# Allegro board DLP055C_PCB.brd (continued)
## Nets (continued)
VX1_DATA6_N: C49.1 U15.D24(VX1_DATA6_N)
VX1_DATA6_P: C50.1 U15.C24(VX1_DATA6_P)
VX1_DATA7_N: C51.1 U15.B25(VX1_DATA7_N)
VX1_DATA7_P: C52.1 U15.A25(VX1_DATA7_P)
VX1_PROJ_ON: J3.22 J68.2
WRP_CAMERA_TRIG: J503.3 R675.1(N1)
N30083522: R673.2(N2) U15.AC28(SSP0_CSZ_2)
N30083525: R672.2(N2) U15.AC26(SSP0_CSZ_1)
N30120583: Q10.4(D4) R739.1 U555.28(ISEN)
N30120605: C752.1 U555.21(VCP)
N30120666: C756.2 U555.17(CP2)
N30120670: C756.1 U555.18(CP1)
N30120672: Q10.1(G) U555.26(GDC)
N30120689: D30.2(CATHODE) L515.1 Q10.3(S) U555.25(LXC)
N30120771: L515.2 R740.1 R742.2
N30120877: R742.1 R747.2 TP228.1 U555.30(/FBC)
N30121099: Q11.1(G) U555.33(GD2)
N30121105: Q11.3(S) R744.2 R750.2
N30121107: R750.1 R751.2 TP230.1 U555.32(FB2)
N30121177: R175.1 R184.2
N30121238: L516.1 R181.2 R184.1
N30121260: R175.2 U555.46(V2P5)
N30121264: D32.2(CATHODE) L516.2 R176.1
N30121280: C763.1 R179.2 R181.1
N30121294: R176.2 U555.41(LX25)
N30121351: L517.1 R752.1 R758.2
N30121367: L518.1 R754.2 R759.2
N30121371: R754.1 R756.2
N30121469: R752.2 R755.2
N30121485: D35.2(CATHODE) L517.2 U555.23(LX5)
N30121491: D36.2(CATHODE) L518.2 U555.43(LX33)
N30121519: R758.1 TP234.1 U555.24(V5)
N30121523: R759.1 TP235.1 U555.45(V3P3)
N30121878: C767.1 C768.1 C769.1 DN4.3 J515.1 U555.13(CTAP)
N30121880: R763.1 U555.5(TACH)
N30122104: R768.2 U555.12(OUTA)
N30122184: R769.2 U555.15(OUTB)
N30122241: C766.2 L519.1 R770.2
N30122253: R770.1 U555.11(VM)
N30122255: R771.2 U555.16(OUTC)
N30122286: R772.2 U555.1(DOUT)
N30122298: D37.2(CATHODE) L519.2 U555.10(VMSW)
N30122348: C771.2 J516.1 L520.2
N30122394: C772.2 R777.1 U555.8(GMIN)
N30122422: D40.2(CATHODE) L520.1 U555.40(F1SW)
N30122436: R776.2 U555.14(SENSE)
N30122458: C767.2 R773.2
N30122460: C768.2 R774.2
N30122462: C769.2 R775.2
N30122488: D39.2(CATHODE) L521.1 U555.39(F2SW)
N30122494: C770.2 J517.1 L521.2
N30122512: D38.2(CATHODE) L522.1 U555.38(F3SW)
N30122563: C18.2 J518.1 L522.2
N30125467: R778.1 U556.28(ISEN)
N30125481: C773.1 U556.21(VCP)
N30125519: C777.2 U556.17(CP2)
N30125523: C777.1 U556.18(CP1)
N30125543: R779.2 U556.25(LXC)
N30125602: R780.2 U556.41(LX25)
N30125636: R781.1 U556.23(LX5)
N30125638: R782.2 U556.43(LX33)
N30125770: C780.1 C781.1 C782.1 DN8.3 J519.1 U556.13(CTAP)
N30125772: R783.1 U556.5(TACH)
N30125789: R784.1 U556.6(OSC)
N30125944: R785.2 U556.12(OUTA)
N30126008: R786.2 U556.35(PWRGOOD)
N30126042: R787.2 U556.15(OUTB)
N30126057: R788.2 U556.34(POSENSE)
N30126109: R789.2 U556.1(DOUT)
N30126111: R790.2 U556.48(RESETZ)
N30126115: C779.2 L523.1 R791.2
N30126127: R791.1 U556.11(VM)
N30126129: R792.2 U556.16(OUTC)
N30126176: R793.2 U556.36(PMDINTZ)
N30126180: C785.2 J520.1 L524.2
N30126190: D41.2(CATHODE) L523.2 U556.10(VMSW)
N30126220: D44.2(CATHODE) L524.1 U556.40(F1SW)
N30126261: C786.2 R798.1 U556.8(GMIN)
N30126303: R797.2 U556.14(SENSE)
N30126331: D43.2(CATHODE) L525.1 U556.39(F2SW)
N30126337: C784.2 J521.1 L525.2
N30126343: C780.2 R794.2
N30126345: C781.2 R795.2
N30126347: C782.2 R796.2
N30126360: D42.2(CATHODE) L526.1 U556.38(F3SW)
N30126390: C783.2 J522.1 L526.2
N30128088: R799.1 U557.28(ISEN)
N30128102: C787.1 U557.21(VCP)
N30128140: C791.2 U557.17(CP2)
N30128144: C791.1 U557.18(CP1)
N30128164: R800.2 U557.25(LXC)
N30128223: R801.2 U557.41(LX25)
N30128257: R802.1 U557.23(LX5)
N30128259: R803.2 U557.43(LX33)
N30128391: C794.1 C795.1 C796.1 DN12.3 J523.1 U557.13(CTAP)
N30128393: R804.1 U557.5(TACH)
N30128410: R805.1 U557.6(OSC)
N30128565: R806.2 U557.12(OUTA)
N30128629: R807.2 U557.35(PWRGOOD)
N30128663: R808.2 U557.15(OUTB)
N30128678: R809.2 U557.34(POSENSE)
N30128730: R810.2 U557.1(DOUT)
N30128732: R811.2 U557.48(RESETZ)
N30128736: C793.2 L527.1 R812.2
N30128748: R812.1 U557.11(VM)
N30128750: R813.2 U557.16(OUTC)
N30128797: R814.2 U557.36(PMDINTZ)
N30128801: C799.2 J524.1 L528.2
N30128811: D45.2(CATHODE) L527.2 U557.10(VMSW)
N30128841: D48.2(CATHODE) L528.1 U557.40(F1SW)
N30128882: C800.2 R819.1 U557.8(GMIN)
N30128924: R818.2 U557.14(SENSE)
N30128952: D47.2(CATHODE) L529.1 U557.39(F2SW)
N30128958: C798.2 J525.1 L529.2
N30128964: C794.2 R815.2
N30128966: C795.2 R816.2
N30128968: C796.2 R817.2
N30128978: D46.2(CATHODE) L530.1 U557.38(F3SW)
N30129011: C797.2 J526.1 L530.2
N30131580: D49.3(CATHODE) FB1.2 FB2.2 J527.2 J528.2 Q12.S(SOURCE) R822.2 R823.2 R824.2 R826.1 TP244.1
N30131609: TP246.1 U519.1(G) U521.9(BFET) U522.4(G)
N30131654: R821.2 U519.2(S) U520.2(A) U568.2(A) U569.2(A)
N30131717: FB1.1 FB2.1 J529.1(V_IN)
N30131761: C801.1 U521.1(DV/DT)
N30131777: R820.1 R827.2 U521.2(EN/UVLO)
N30131888: R828.1 U521.10(ILIM)
N30131961: FB3.2 J529.2(GND#2)
N30131963: FB4.2 J529.3(GND#3)
N30131977: U521.6(OUT#6) U521.7(OUT#7) U521.8(OUT#8) U522.1(S#1) U522.2(S#2) U522.3(S#3)
N30132461: R831.2 U523.3(D)
N30132672: R833.1 U524.1(EN)
N30132680: C812.2 U524.7(VBST)
N30132682: C812.1 L531.1 U524.6(SW)
N30132740: C813.2 C814.2 C815.2 L531.2 R834.1 R836.2
N30132787: C816.2 U524.3(VREG5)
N30132791: C813.1 R108.2 R836.1 U524.2(VFB)
N30132852: C817.2 U524.4(SS)
N30132884: R835.2 U527.3(D)
N30132918: C818.2 U525.5(TADJ)
N30132924: C819.2 U526.5(TADJ)
N30133027: R837.2 U528.3(D)
N30133077: C820.1 U59.1(DV/DT)
N30133183: R838.1 U59.10(ILIM)
N30178636: R872.2 U538.3(IN+) VR1.2(WIPER)
N30178648: C832.2 J532.1 R873.1
N30178650: J532.2 R874.1 TP279.1 U538.2(IN-)
N30178830: R876.2 U566.5(IN+) VR2.2(WIPER)
N30178842: C834.2 J533.1 R877.1
N30178844: J533.2 R878.1 TP281.1 U566.6(IN-)
N30179022: R880.2 U539.3(IN+) VR3.2(WIPER)
N30179034: C836.2 J535.1 R881.1
N30179036: J535.2 R882.1 TP283.1 U539.2(IN-)

Pads without a net: D49 2; D51 2; FID 1; FID#2 1; FID#3 1; FID#4 1; FID#5 1; FID#6 1; J10 46 48; J17 9 10 11 12; J21 6; J70 6 10 12 13 14; J102 9; J103 2 6; J111 4 5; J501 17 19; SW5 2 4 6; U1 1 2; U4 27 28 30 55 56; U8 27 28 30 55 56; U11 1; U12 1; U13 1; U14 1; U15 AJ12 AJ19 B29 C28 C30 D30 R30 T26 T29; U16 1; U17 2 5; U18 1; U19 1; U20 1; U30 1 2; U33 1; U39 1; U40 1; U42 1; U48 1; U51 22 23; U58 1; U59 9; U501 1 2; U503 5 7; U520 1; U525 8; U529 1; U538 5 6 7; U539 5 6 7; U555 29; U556 26 29 33; U557 26 29 33; U558 1; U562 18; U563 1; U564 1; U566 1 2 3; U568 1; U569 1

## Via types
v1: diameter 0.559, hole 0.203, TOP to BOTTOM, 2451 vias

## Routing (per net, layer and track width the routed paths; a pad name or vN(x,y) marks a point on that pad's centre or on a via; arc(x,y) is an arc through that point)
GND: length 3023.6
  TOP w0.203: J42.33 v1(146.38,9.01) ; J10.4 179.69,53.1 v1(179.64,53.05) ; v1(27.51,74.63) 26.83,75.31 U562.24 ; U559.2 16.58,100.43 16.29,100.71 v1(15.76,100.71) ; Q6.2 169.77,51.93 v1(169.79,51.94) ; J10.39 v1(179.63,70.6) ; J10.9 179.71,55.6 v1(179.68,55.62) ; v1(27.62,53.34) 27.51,53.46 U556.44 ; J10.1 v1(179.68,51.6) ; v1(179.62,119.94) 179.81,120.13 J7.39 ; J42.9 134.37,8.94 v1(134.44,9) ; v1(135.95,9.07) 135.88,9 J42.12 ; J10.13 179.7,57.6 v1(179.69,57.61) ; U557.19 v1(76.77,95.07) ; U27.2 34.87,73.27 C530.1 ; J10.20 179.7,61.1 v1(179.68,61.08) ; J10.5 v1(178.78,53.6) ; v1(83.76,95.2) 84.1,95.54 U525.4 ; J10.16 179.74,59.1 v1(179.72,59.07) ; U557.7 v1(70.63,100.71) ; J7.42 179.96,121.63 179.53,122.06 178.71,122.06 v1(178.15,121.5) ; v1(179.69,63.07) 179.72,63.1 J10.24 ; U17.4 12.29,93.47 v1(12.59,93.17) ; J42.6 132.88,8.73 132.87,8.74 132.87,9.16 132.88,9.17 v1(132.88,9.63) ; v1(179.64,69.05) 179.69,69.1 J10.36 ; v1(179.78,77.12) 180.3,76.6 J10.51 ; v1(28.77,45.73) 28.51,46 U556.19 ; v1(36.69,83.21) 37.05,83.57 U561.2 ; J42.18 v1(138.88,9.19) ; U501.4 v1(17.97,77.34) ; J10.21 v1(178.73,61.6) ; J42.45 v1(152.38,9.05) ; v1(22.17,51.52) 22.46,51.52 22.79,51.18 U556.7 ; J10.17 v1(178.84,59.6) ; J10.28 179.76,65.1 v1(179.72,65.06) ; J10.25 v1(178.82,63.6) ; J42.30 v1(144.87,8.99) ; J10.29 v1(179.02,65.6) ; J42.27 v1(143.37,9.01) ; U26.49 24.97,108.05 v1(25.02,108) ; J42.15 v1(137.37,9.09) ; J42.39 v1(149.38,9.05) ; J42.21 v1(140.38,8.99) ; U557.44 75.77,102.99 v1(75.88,102.87) ; J10.32 179.6,67.1 v1(179.57,67.07) ; U525.3 v1(83.68,96.19) ; J10.12 v1(179.04,57.1) ; J10.50 v1(179.69,76.1) ; J42.42 v1(150.87,9.06) ; J42.24 v1(141.88,9.01) ; J42.7 v1(133.37,8.95) ; J10.42 v1(179.63,72.1) ; J42.48 v1(153.87,9.08) ; v1(61.66,59) 61.86,58.8 U555.7 ; J10.33 v1(178.86,67.6) ; 147.87,7.61 v1(147.87,9.03) ; J10.8 v1(178.93,55.1)
  TOP w0.254: J7.5 180,103.13 v1(179.72,102.84) 179.94,102.63 J7.4 ; U51.10 v1(126.7,32.81) ; J7.12 179.92,106.63 v1(179.67,106.88) 179.91,107.13 J7.13 ; J69.14 6.55,121.68 v1(6.64,121.76) ; J500.37 v1(64.87,9.05) ; J7.33 179.93,117.13 179.68,116.87 ; J500.29 v1(60.87,8.96) ; J500.1 46.87,8.46 v1(46.44,8.89) ; J44.25 v1(100.15,9.01) ; J69.9 6.59,119.18 v1(6.79,119.38) ; 127.41,142.94 127.16,143.2 J3.6 ; 127.41,142.94 127.41,142.95 127.66,143.19 J3.5 ; 127.41,142.94 v1(127.41,142.86) ; U51.21 v1(132.2,32.78) ; J500.51 71.87,8.56 v1(72.4,9.09) ; J7.8 179.92,104.63 v1(179.69,104.85) 179.97,105.13 J7.9 ; J500.45 v1(68.87,8.99) ; J7.16 179.75,108.63 v1(179.51,108.86) 179.78,109.13 J7.17 ; J28.7 v1(180.91,5.21) ; J500.19 v1(55.87,9.12) ; 179.68,116.87 179.71,116.87 179.96,116.63 J7.32 ; 179.68,116.87 v1(179.58,116.87) ; U4.52 141.33,133.68 141.32,133.67 140.9,133.67 140.89,133.68 v1(140.71,133.68) ; J3.36 v1(112.16,142.76) ; J500.43 v1(67.87,8.89) ; J28.5 v1(179.91,5.2) ; U4.33 141.05,143.18 v1(140.96,143.27) ; U51.27 v1(132.7,40.18) ; J500.41 v1(66.87,9.07) ; U26.14 v1(23.97,124.51) ; J500.39 v1(65.87,9.07) ; J44.48 v1(111.65,8.86) ; J28.9 v1(181.91,5.31) ; v1(121.94,37.1) 122.2,37.36 U51.48 ; J44.33 v1(104.15,9.09) ; J17.8 v1(183.1,38.85) ; v1(178.86,7.51) 178.91,7.46 J28.3 ; J500.11 v1(51.87,8.97) ; J500.13 v1(52.87,8.92) ; 179.66,114.89 179.9,115.13 J7.29 ; 179.66,114.89 179.92,114.63 J7.28 ; 179.66,114.89 v1(179.65,114.9) ; U26.68 v1(30.74,114.96) ; v1(24.83,74.53) 24.83,74.53 U562.20 24.83,77.86 ; U51.15 v1(129.2,32.68) ; J44.22 v1(98.65,9.11) ; 24.83,77.86 U562.33 ; 24.83,77.86 23.33,76.36 U562.17 v1(23.33,74.52) ; U562.33 26.83,76.36 U562.24 ; U562.33 25.33,78.35 U562.4 25.33,81.34 25.18,81.5 25.18,81.51 25.08,81.61 v1(25.08,81.67) ; J500.3 v1(47.87,9) ; U8.33 141.18,125.08 v1(141.06,125.21) ; J44.43 v1(109.15,8.93) ; J500.17 v1(54.87,9.02) ; U51.1 v1(122.2,32.8) ; J500.21 v1(56.87,9.13) ; J28.11 v1(182.91,5.31) ; J69.10 v1(4.11,119.68) ; v1(68.2,53.22) 68.17,53.22 68.07,53.32 68.07,53.46 68.03,53.51 68.03,53.6 67.92,53.71 67.92,54.57 U555.19 ; J44.16 v1(95.65,9.01) ; J3.39 v1(110.66,142.76) ; J500.9 v1(50.87,8.92) ; J42.5 132.37,8.89 v1(132.34,8.93) ; U26.61 33.51,111.46 v1(33.88,111.08) ; v1(179.49,101.12) 179.5,101.13 J7.1 ; U555.44 v1(66.88,64.99) ; U51.25 133.7,40.21 v1(133.79,40.3) ; U51.39 v1(126.7,37.09) ; J500.47 v1(69.87,8.99) ; J3.33 v1(113.66,142.81) ; J7.24 179.92,112.63 v1(179.67,112.88) 179.92,113.13 J7.25 ; J3.8 v1(126.16,142.83) ; U51.28 v1(132.2,37.24) ; J500.25 v1(58.87,9.22) ; J500.5 v1(48.87,8.89) ; J44.19 v1(97.15,9.06) ; v1(179.47,118.63) J7.36 ; v1(169.71,45.02) 169.71,45.02 U34.2 ; J3.24 v1(118.16,142.87) ; J3.10 125.16,142.81 v1(125.15,142.81) ; J500.49 v1(70.87,9.06) ; J500.23 v1(57.87,9.14) ; U51.45 v1(123.7,40.21) ; J500.15 v1(53.87,8.89) ; J500.7 v1(49.87,8.89) ; J500.27 v1(59.87,9.03) ; J44.39 v1(107.15,9.17) ; U51.26 v1(133.2,37.24) ; J3.48 v1(106.16,142.82) ; J44.27 v1(101.15,9.08) ; J7.21 179.87,111.13 v1(179.59,110.85) 179.81,110.63 J7.20 ; J3.42 v1(109.16,142.81) ; J3.30 v1(115.16,142.83) ; v1(116.59,142.79) 116.66,142.86 J3.27 ; J500.31 v1(61.87,9.05) ; U8.52 v1(144.33,115.58) ; J500.35 v1(63.87,9.02) ; J500.33 v1(62.87,9.12) ; U26.19 v1(21.47,124.47) ; J44.45 v1(110.15,8.86) ; U51.4 v1(123.7,32.78) ; J3.51 v1(104.66,142.86) ; U51.24 v1(133.7,32.78) ; U51.34 v1(129.2,37.19) ; J44.13 v1(94.15,8.94) ; J3.45 v1(107.66,142.77) ; J44.10 v1(92.65,9.09) ; J3.15 v1(122.66,142.83) ; J3.19 v1(120.66,142.87)
  TOP w0.305: C665.2 11.19,30.12 U46.15 ; U15.D25 139.87,98.33 139.02,98.33 U15.C25
  TOP w0.381: U15.A13 v1(136.45,85.9) ; U560.1 v1(38.42,76.2) ; U15.J3 v1(144.45,75.9) ; U15.A11 v1(136.45,83.9) ; U43.12 126.28,63.24 v1(126.24,63.19) ; J500.55 v1(76.83,2.55) ; U3.3 v1(76.13,139.06) ; U15.E3 v1(140.45,75.9) ; C831.1 125.41,121.16 v1(125.21,121.36) ; J3.60 v1(111.09,149.21) ; U15.R16 v1(150.45,89.9) ; U15.AF14 v1(162.45,86.9) ; U15.N12 v1(148.45,84.9) ; U15.AB6 v1(158.45,78.9) ; v1(166.55,75.9) 166.45,75.9 U15.AK3 ; v1(166.66,84.45) 166.61,84.4 U15.AK11 ; VR3.1 v1(135.43,111.01) ; U15.AK7 v1(166.65,80.4) ; v1(186.19,70.33) 186.19,71.44 J10.60 ; U15.AA25 v1(157.45,98.9) ; J44.60 v1(106.81,2.55) ; U15.AE28 v1(161.45,101.9) ; v1(133.97,63.27) 133.43,63.81 U43.1 ; v1(178.66,88.89) 178.61,88.94 178.61,88.94 178.61,89.07 178.45,89.22 U12.3 ; U15.E28 v1(140.45,101.9) ; J3.59 v1(115.92,149.21) ; U15.E15 v1(140.45,87.9) ; v1(66.19,139.19) 66.07,139.06 U2.3 ; U15.T6 v1(152.45,78.9) ; C793.1 68.35,91.13 68.77,90.7 69.33,90.7 v1(69.56,90.47) ; U15.AF3 v1(162.45,75.9) ; 141.84,69.85 141.84,69.23 141.45,68.85 v1(140.8,68.85) ; 141.84,69.85 141.84,70.52 141.53,70.83 v1(140.8,70.83) ; 141.84,69.85 C95.2 ; 141.84,69.85 v1(140.8,69.85) ; U15.AF26 v1(162.45,99.9) ; J42.58 v1(139.08,2.55) ; C624.2 v1(20.43,74.15) ; J500.60 v1(65.56,2.55) ; J42.52 v1(125.39,7.61) ; U527.2 v1(88.63,89.87) ; C34.2 153.58,107.63 ; 153.58,107.63 153.58,108.07 153.04,108.61 v1(152.55,108.61) ; 153.58,107.63 153.58,107.01 153.2,106.63 v1(152.55,106.63) ; 153.58,107.63 v1(152.55,107.63) ; v1(55.03,10.14) 54.93,10.24 R545.2 ; J44.57 v1(91.77,2.55) ; J44.63 v1(82.25,6.69) ; 132.72,75.65 133.39,75.65 133.69,75.96 v1(133.69,76.82) ; 132.72,75.65 132.09,75.65 131.71,76.03 v1(131.71,76.68) ; 132.72,75.65 v1(132.72,76.68) ; 132.72,75.65 C91.2 ; U13.3 88.66,28.24 v1(88.57,28.15) ; U15.AG10 v1(163.45,82.9) ; U15.B3 v1(137.45,75.9) ; J44.55 v1(118.21,2.55) ; U15.B5 v1(137.45,77.9) ; U15.P12 v1(149.45,84.9) ; C127.2 v1(170.69,59.05) ; U15.W13 v1(155.45,85.9) ; v1(83.86,146) 83.85,146.01 J2.5 ; U15.AF12 v1(162.45,84.9) ; v1(169.43,94.15) 169.34,94.07 C69.1 ; U15.N14 v1(148.45,86.9) ; U15.M15 v1(147.45,87.9) ; R62.2 163.85,52.64 v1(163.84,52.63) ; J10.53 v1(179.64,79.6) ; J42.63 124.47,4.94 124.9,5.37 v1(124.9,6.63) ; U15.W5 v1(155.45,77.9) ; U15.T12 v1(152.45,84.9) ; SW5.3 v1(52.34,148.59) ; J7.52 v1(179.67,98.13) ; U15.G5 v1(142.45,77.9) ; J500.52 v1(41.86,7.61) ; VR2.1 v1(99.97,128.16) ; J500.57 v1(50.49,2.55) ; U19.3 v1(94.58,34.28) ; DN1.1 v1(54.17,35.92) ; J44.59 v1(101.78,2.55) ; J7.55 186.04,130.93 v1(186.13,131.02) ; U15.F17 v1(141.45,90.9) ; J42.55 v1(160.52,2.55) ; U47.3 v1(138.69,56.84) ; U15.Y6 v1(156.45,78.9) ; U15.E20 v1(140.45,93.9) ; U560.4 v1(38.44,80.01) ; U15.H6 v1(143.45,78.9) ; U15.AB30 v1(158.45,103.9) ; U15.AK15 v1(166.45,87.9) ; U15.AH2 v1(164.45,74.9) ; U15.V17 v1(154.45,90.9) ; C27.1 90.4,116.84 ; 90.4,116.84 90.4,117.51 90.09,117.82 v1(89.37,117.82) ; 90.4,116.84 90.4,116.22 90.02,115.84 v1(89.37,115.84) ; 90.4,116.84 v1(89.37,116.84) ; FB4.1 v1(20.64,139.93) ; FB4.1 v1(22.24,137.59) ; FB4.1 v1(18.83,137.59) ; FB4.1 v1(20.64,135.51) ; v1(166.68,99.4) U15.AK26 U15.AJ26 ; J7.56 v1(186.04,102.33) ; v1(9.24,36.97) J102.5 ; 132.72,84.05 132.04,84.05 131.66,83.67 v1(131.66,83.02) ; 132.72,84.05 v1(132.72,83.02) ; 132.72,84.05 133.36,84.05 133.74,83.67 v1(133.74,82.96) ; 132.72,84.05 C74.2 ; U15.AF18 v1(162.45,91.9) ; U15.R27 v1(150.45,100.9) ; U15.A30 v1(136.45,103.9) ; U15.M17 v1(147.45,90.9) ; U15.AH4 v1(164.45,76.9) ; U15.D19 v1(139.45,92.9) ; U15.C23 v1(138.45,96.9) ; C692.2 v1(21.59,28.16) ; U15.U14 v1(153.45,86.9) ; U15.B1 v1(137.45,73.9) ; U15.P13 v1(149.45,85.9) ; v1(29.49,79.92) 29.56,80 U563.3 ; C677.2 v1(173.04,119.42) ; U15.T14 v1(152.45,86.9) ; J44.58 v1(96.85,2.55) ; 176.44,143.19 C1.2 ; 176.44,143.19 v1(175.41,143.19) ; 176.44,143.19 176.44,143.86 176.14,144.17 v1(175.41,144.17) ; 176.44,143.19 176.44,142.57 176.06,142.19 v1(175.41,142.19) ; U15.R19 v1(150.45,92.9) ; U15.W19 v1(155.45,92.9) ; U15.F10 v1(141.45,82.9) ; J7.59 v1(186.04,114.89) ; U15.A2 v1(136.45,74.9) ; J12.4 v1(113.95,41.85) ; U15.M26 v1(147.45,99.9) ; v1(186.18,75.4) 186.18,76.46 J10.61 ; U16.3 v1(178.45,84.39) ; U15.K6 v1(145.45,78.9) ; U15.P19 v1(149.45,92.9) ; U15.AE7 v1(161.45,79.9) ; J500.53 v1(76.86,7.61) ; J42.62 v1(161.28,6.67) ; U15.AE9 v1(161.45,81.9) ; v1(103.62,59.66) 103.93,59.35 J115.1 ; U560.2 v1(38.62,77.47) ; U15.AG23 v1(163.45,95.9) U15.AH23 ; J10.52 180.76,48.36 v1(179.58,48.36) ; C514.2 v1(18.11,97.04) ; J3.62 v1(98.76,145.35) ; U15.N19 v1(148.45,92.9) ; C678.2 176.21,119.43 v1(176.31,119.34) ; U15.D23 v1(139.45,96.9) ; J7.53 v1(179.67,129.13) ; J10.59 186.19,66.44 v1(186.19,65.42) ; U15.E5 v1(140.45,77.9) ; U15.W25 v1(155.45,98.9) ; J7.57 v1(186.04,107.38) ; U15.R14 v1(150.45,86.9) ; U15.AC27 v1(159.45,100.9) ; U35.13 v1(144.02,43.17) ; U15.AG14 v1(163.45,86.9) ; R714.2 v1(169.86,112.9) ; J42.54 v1(125.53,2.55) ; J10.56 186.3,51.85 v1(186.3,52.95) ; U15.AA28 v1(157.45,101.9) ; U15.AJ9 v1(164.45,82.9) U15.AH10 ; U15.AF6 v1(162.45,78.9) ; U15.A22 v1(136.22,95.4) ; U15.V6 v1(154.45,78.9) ; C504.1 v1(174.31,24.13) ; U15.AH29 v1(164.45,102.9) ; U38.2 v1(71.44,11.54) ; U15.AG29 v1(163.45,102.9) ; J7.58 v1(186.04,112.31) ; R525.1 v1(181.18,28.71) ; U15.F12 v1(141.45,84.9) ; J114.3 v1(148.25,54.83) ; R643.2 v1(160.77,69.33) ; U15.AJ1 v1(165.45,73.9) ; U15.AH16 v1(164.45,89.9) ; U15.V30 v1(154.45,103.9) ; U15.U18 v1(153.45,91.9) ; U15.B24 v1(137.45,97.9) ; U15.AJ30 v1(165.45,103.9) ; J2.6 v1(77.08,149.9) ; U15.AG4 v1(163.45,76.9) ; U15.A1 v1(136.45,73.9) ; U15.AF22 v1(162.45,95.9) ; U15.AH25 v1(164.45,97.9) ; C779.1 v1(20.64,40.54) ; U15.AG8 v1(163.45,80.9) ; 176.44,132.4 176.44,131.78 176.06,131.39 v1(175.41,131.39) ; 176.44,132.4 C8.2 ; 176.44,132.4 v1(175.41,132.4) ; 176.44,132.4 176.44,133.07 176.14,133.38 v1(175.41,133.38) ; U15.AJ3 v1(165.45,75.9) ; J44.62 119.05,6.11 v1(118.81,6.35) ; U15.E13 v1(140.45,85.9) ; U526.3 v1(81.01,91.11) ; U15.A28 v1(136.45,101.9) ; U15.R15 v1(150.45,87.9) ; C669.2 v1(171.13,131.01) ; C665.2 v1(10.22,30.05) ; U15.A29 v1(136.45,102.9) ; C60.1 v1(65.8,117.91) ; U15.F13 v1(141.45,85.9) ; U15.F20 v1(141.45,93.9) ; U15.AK30 v1(166.45,103.9) ; U15.C8 v1(138.45,80.9) ; U15.M14 v1(147.45,86.9) ; U15.U5 v1(153.45,77.9) ; U15.AH3 v1(164.45,75.9) ; U15.E11 v1(140.45,83.9) ; U15.AE23 v1(161.45,96.9) ; U15.B7 v1(137.45,79.9) ; U15.B11 v1(137.45,83.9) ; v1(82,28.36) 82.2,28.56 U18.3 ; C133.2 v1(142.56,40.7) ; U30.7 v1(105.09,54.23) ; U15.L25 v1(146.45,98.9) ; U15.AJ17 v1(165.45,90.9) ; C801.2 59.79,124.15 v1(58.82,123.17) ; J10.55 186.19,79.75 v1(186.19,81.48) ; R644.2 164,71.29 v1(164,70.7) ; D41.1 v1(12.56,50.16) ; J20.6 v1(105.99,22.74) ; U15.E22 v1(140.45,95.9) ; U15.V19 v1(154.45,92.9) ; U15.D1 v1(139.45,73.9) ; U15.A3 v1(136.45,75.9) ; C808.1 v1(75.45,130.78) ; U15.N16 v1(148.45,89.9) ; DN4.1 v1(57.98,40.41) ; U15.N13 v1(148.45,85.9) ; U15.AF10 v1(162.45,82.9) ; U15.T13 v1(152.45,85.9) ; U15.P30 v1(149.45,103.9) ; J7.61 v1(186.04,124.97) ; U15.N15 v1(148.45,87.9) ; U15.AK1 v1(166.45,73.9) ; J536.4 v1(169.2,37.49) ; U15.M13 v1(147.45,85.9) ; U564.3 v1(46.2,84.47) ; U15.AF24 v1(162.45,97.9) ; U15.AF5 v1(162.45,77.9) ; v1(151.3,68.8) 150.65,68.8 150.26,69.18 150.26,69.85 ; U15.AE25 v1(161.45,98.9) ; J21.1 v1(131.18,23.42) ; U15.D2 v1(139.45,74.9) ; U15.W18 v1(155.45,91.9) ; U43.13 v1(126.28,60.09) ; U15.U19 v1(153.45,92.9) ; R865.2 60.91,141.72 v1(60.99,141.63) ; U15.T17 v1(152.45,90.9) ; U15.F2 v1(141.45,74.9) ; C766.1 61.98,51.5 v1(62.4,51.93) ; U15.B18 v1(138.45,90.9) U15.C17 ; v1(165.98,56.62) 165.96,56.6 C126.2 R63.2 ; J500.58 v1(55.6,2.55) ; 150.26,69.85 v1(151.3,69.85) ; 150.26,69.85 C97.2 ; 150.26,69.85 150.26,70.5 150.65,70.88 151.24,70.88 v1(151.3,70.83) ; U15.AG12 v1(163.45,84.9) ; U15.AJ5 v1(164.45,78.9) U15.AH6 ; DN5.1 v1(27.62,29.67) ; J7.54 v1(186.04,96.35) ; J533.3 v1(99.99,120.33) ; U15.M16 v1(147.45,89.9) ; 143.91,69.85 C96.2 ; 143.91,69.85 143.91,70.5 144.3,70.88 v1(144.95,70.88) ; 143.91,69.85 143.91,69.18 144.3,68.8 v1(144.95,68.8) ; 143.91,69.85 v1(144.95,69.85) ; U15.AK13 v1(166.45,85.9) ; U40.3 v1(45.95,88.28) ; U15.D17 v1(139.45,90.9) ; U15.AJ28 U15.AK28 v1(166.7,101.4) ; U15.F6 v1(141.45,78.9) ; C664.1 v1(143.31,60.13) ; U15.R13 v1(150.45,85.9) ; U15.AE21 v1(161.45,94.9) ; U15.G27 v1(142.45,100.9) ; C700.1 v1(173.53,113.78) ; U15.AH14 v1(164.45,86.9) ; U15.T1 v1(152.45,73.9) ; U15.M12 v1(147.45,84.9) ; U15.V15 v1(154.45,87.9) ; U15.J4 v1(144.45,76.9) ; VR1.1 126.29,130.39 126.96,131.06 126.96,131.52 v1(127.34,131.9) ; J42.61 v1(154.05,2.55) ; U15.U25 v1(153.45,98.9) ; U15.AE1 v1(161.45,73.9) ; U15.N25 v1(148.45,98.9) ; C806.1 v1(76.62,134.62) ; U15.D25 v1(140.45,97.9) U15.E24 ; R827.1 v1(59,120.68) ; U49.1 v1(116.92,69.07) ; U15.W1 v1(155.45,73.9) ; X1.2 v1(171.87,90) ; U15.A9 v1(136.45,81.9) ; U15.AF28 v1(162.45,101.9) ; U15.M3 v1(147.45,75.9) ; U15.D14 v1(139.45,86.9) ; U15.AJ15 v1(165.45,87.9) ; U15.AG6 v1(163.45,78.9) ; U15.A15 v1(136.45,87.9) ; U15.AE17 v1(161.45,90.9) ; U15.D10 v1(139.45,82.9) ; U42.3 v1(46.12,92.09) ; U15.AH12 v1(164.45,84.9) U15.AJ11 ; U15.AH27 v1(164.45,99.9) ; U15.B22 v1(138.45,94.9) U15.C21 ; U15.AC3 v1(159.45,75.9) ; C668.2 v1(177.48,128.85) ; U15.N18 v1(148.45,91.9) ; v1(166.73,97.4) U15.AK24 U15.AJ24 ; U15.P16 v1(149.45,89.9) ; U15.W12 v1(155.45,84.9) ; v1(128.28,109.4) 128.59,109.7 J535.3 ; U15.N17 v1(148.45,90.9) ; R586.1 v1(16.06,105.53) ; v1(109.68,63.66) 109.77,63.75 U49.13 ; U15.F5 v1(141.45,77.9) ; U15.B9 v1(137.45,81.9) ; J10.54 186.19,48.44 v1(186.19,46.86) ; U15.A20 v1(136.2,93.4) ; U15.H2 v1(143.45,74.9) ; J500.62 v1(77.77,6.51) ; U15.V16 v1(154.45,89.9) ; U15.G3 v1(142.45,75.9) ; J3.52 v1(132.66,142.76) ; U15.W16 v1(155.45,89.9) ; U15.AG25 v1(163.45,97.9) ; U15.D21 v1(139.45,94.9) ; U15.B2 v1(137.45,74.9) ; U15.AH30 v1(164.45,103.9) ; R715.2 v1(171.77,112.9) ; U15.D28 v1(139.45,101.9) ; U15.AC25 v1(159.45,98.9) ; U15.B20 v1(138.45,92.9) U15.C19 ; J44.61 v1(111.81,2.55) ; C670.2 v1(177.37,94.37) ; v1(66.51,135.89) C807.1 ; U14.3 v1(94.55,38.4) ; R88.2 v1(57.78,141.72) ; J3.63 v1(135.56,145.35) ; U15.V14 v1(154.45,86.9) ; U15.D6 v1(139.45,78.9) ; U15.AE15 v1(161.45,87.9) ; U15.AH21 v1(164.45,93.9) ; U15.B26 U15.A26 136.2,99.4 v1(136.19,99.41) ; U15.U13 v1(153.45,85.9) ; J3.55 v1(99.72,149.21) ; U15.AH18 v1(164.45,91.9) ; v1(107.88,49.27) 107.63,49.03 U30.4 ; U15.E23 v1(140.45,96.9) ; U15.J25 v1(144.45,98.9) ; U15.A5 v1(136.45,77.9) ; U15.L1 v1(146.45,73.9) ; U15.R3 v1(150.45,75.9) ; U49.12 109.77,71.47 v1(109.11,72.14) ; J42.57 v1(133.99,2.55) ; R830.2 v1(54.95,140.97) ; U38.3 v1(73.32,12.62) ; DN6.1 v1(30.8,29.67) ; U15.U16 v1(153.45,89.9) ; C772.1 v1(58.74,62.76) ; U15.F30 v1(141.45,103.9) ; v1(70.07,119.67) 70.49,119.26 C799.1 ; U15.AE5 v1(161.45,77.9) ; U15.V13 v1(154.45,85.9) ; U15.AG18 v1(162.45,90.9) U15.AF17 ; J44.53 v1(118.16,7.61) ; U15.B30 v1(137.45,103.9) ; U15.L27 v1(146.45,100.9) ; U15.L26 v1(146.45,99.9) ; U15.H1 v1(143.45,73.9) ; U15.AG16 v1(163.45,89.9) ; U15.V12 v1(154.45,84.9) ; J16.4 v1(113.95,34.88) ; C530.1 33.84,73.55 v1(33.83,73.55) ; U15.AK9 v1(166.65,82.4) ; J42.60 v1(148.8,2.55) ; U15.K30 v1(145.45,103.9) ; U15.E25 v1(140.45,98.9) ; J500.61 v1(70.51,2.55) ; J500.54 v1(41.96,2.55) ; R2.2 v1(74.72,143.51) ; J42.59 v1(143.92,2.55) ; FB3.1 v1(35.34,138.86) ; FB3.1 v1(37.15,136.83) ; FB3.1 v1(37.15,141.2) ; FB3.1 v1(38.82,138.86) ; U15.AJ7 v1(164.45,80.9) U15.AH8 ; C684.1 182.91,90.17 v1(183.31,89.77) ; J44.56 v1(89.38,2.55) ; J7.63 v1(182.23,95.23) ; J42.56 v1(131.98,2.55) ; U560.3 v1(38.62,78.74) ; U15.N1 v1(148.45,73.9) ; C784.1 v1(32.38,70.37) ; DN8.1 v1(33.97,29.67) ; U15.W27 v1(155.45,100.9) ; U15.AJ13 v1(165.45,85.9) ; U15.AF19 v1(162.45,92.9) U15.AF20 ; X1.4 v1(174.76,93.49) ; U15.M19 v1(147.45,92.9) ; J500.63 v1(40.97,6.61) ; U15.C12 v1(138.45,84.9) ; J10.58 186.14,61.69 v1(186.14,62.99) ; U15.W15 v1(155.45,87.9) ; U15.C4 v1(138.45,76.9) ; U15.U12 v1(153.45,84.9) ; U15.AK5 v1(166.65,78.4) ; U15.AF30 v1(162.45,103.9) ; U15.U17 v1(153.45,90.9) ; U15.E7 v1(140.45,79.9) ; U15.B28 v1(137.45,101.9) ; J27.2 v1(183.62,19.08) ; U15.AD6 v1(160.45,78.9) ; U15.C29 v1(138.45,102.9) ; J7.62 v1(182.25,132.03) ; U15.V18 v1(154.45,91.9) ; U15.AJ22 v1(164.45,95.9) ; C694.2 v1(20.75,34.81) ; C679.2 v1(174.31,128.78) ; R712.2 v1(150.94,62.34) ; U15.P18 v1(149.45,91.9) ; v1(80.78,144.09) 80.85,144.01 U1.4 ; DN3.1 v1(42.33,36.36) ; C763.2 v1(47.42,75.52) ; J3.58 v1(118.36,149.21) ; J3.61 v1(105.91,149.21) ; J3.54 v1(134.56,149.21) ; J532.3 v1(130.51,132.49) ; R544.2 v1(65.72,12.9) ; C503.1 180.71,25.92 v1(181,25.64) ; U15.M6 v1(147.45,78.9) ; U15.A24 v1(136.45,97.9) ; U15.T19 v1(152.45,92.9) ; U15.D12 v1(139.45,84.9) ; U15.C10 v1(138.45,82.9) ; U15.AE26 v1(161.45,99.9) ; J44.54 v1(83.11,2.55) ; U15.AF15 v1(162.45,87.9) ; U15.R17 v1(150.45,90.9) ; U15.H5 v1(143.45,77.9) ; U15.W17 v1(155.45,90.9) ; U15.AB1 v1(158.45,73.9) ; J44.52 v1(83.14,7.61) ; v1(169.6,89.27) 169.34,89.54 C70.1 ; U15.J5 v1(144.45,77.9) ; U565.3 v1(60.96,145.83) ; DN2.1 v1(57.98,35.97) ; U15.U15 v1(153.45,87.9) ; U47.1 v1(138.76,58.73) ; J7.60 v1(186.04,119.97) ; U15.E9 v1(140.45,81.9) ; U15.F1 v1(141.45,73.9) ; U15.C3 v1(138.45,75.9) ; U15.U3 v1(153.45,75.9) ; v1(186.18,57.97) 186.18,56.73 J10.57 ; U15.T15 v1(152.45,87.9) ; J500.56 v1(48.36,2.55) ; U15.M18 v1(147.45,91.9) ; U15.AH1 v1(164.45,73.9) ; J10.62 v1(182.19,82.5) ; U15.A18 v1(136.45,90.9) ; U15.G4 v1(142.45,76.9) ; U15.D8 v1(139.45,80.9) ; U15.N28 v1(148.45,101.9) ; U15.C6 v1(138.45,78.9) ; C797.1 v1(92.5,108.91) ; J500.59 v1(60.38,2.55) ; U15.AF8 v1(162.45,80.9) ; U15.P15 v1(149.45,87.9) ; U15.R12 v1(150.45,84.9) ; U15.E21 v1(140.45,94.9) ; DN7.1 v1(24.45,29.67) ; J42.53 v1(160.52,7.61) ; U15.P6 v1(149.45,78.9) ; C798.1 v1(76.2,119.59) ; U15.F8 v1(141.45,80.9) ; J10.63 v1(182.06,45.7) ; U15.A7 v1(136.45,79.9) ; U15.J28 v1(144.45,101.9) ; U15.P17 v1(149.45,90.9) ; DN11.1 v1(70.48,91.12) ; J3.53 v1(101.66,142.81) ; J3.56 v1(128.29,149.21) ; U15.F18 v1(141.45,91.9) ; R524.1 v1(172.24,27.42) ; C785.1 v1(23.52,63.19) ; U20.3 v1(94.56,30.15) ; U33.3 v1(164.85,49.53) ; U15.C14 v1(138.45,86.9) ; U15.T18 v1(152.45,91.9) ; U15.B13 v1(137.45,85.9) ; U15.P14 v1(149.45,86.9) ; U55.3 v1(138.43,33.62) ; J2.7 v1(86.64,148.35) ; U15.Y3 v1(156.45,75.9) ; U15.AE11 v1(161.45,83.9) ; U15.AK22 v1(166.73,95.4) ; U39.3 v1(79.79,12.62) ; U15.T16 v1(152.45,89.9) ; U15.AG27 v1(163.45,99.9) ; J3.57 v1(123.44,149.21) ; U15.U28 v1(153.45,101.9) ; C809.1 v1(53.86,136.96) ; U15.AK17 v1(166.45,90.9) ; D30.1 v1(73.34,45.44) ; U15.R18 v1(150.45,91.9) ; U15.E4 v1(140.45,76.9) ; U15.R25 v1(150.45,98.9) ; U15.G25 v1(142.45,98.9) ; U15.W14 v1(155.45,86.9)
  TOP w0.635: D35.1 v1(62.98,43.83) ; v1(70.7,107.42) 70.7,108.59 D48.1 ; C760.2 v1(97.34,43.81) ; D37.1 v1(51.85,57.15) ; C783.1 v1(40.3,46.99) ; U521.11 64.98,127 v1(65.49,126.5) ; C59.2 79.74,137.87 79.74,139.52 v1(80.2,139.98) ; C770.1 v1(75.88,69.16) ; D46.1 v1(90.82,105.41) ; D40.1 v1(60.92,80.01) ; C18.1 v1(78.77,68.24) ; v1(87.25,35.34) 86.99,35.09 C764.1 ; C761.2 v1(97.34,54.94) ; D38.1 v1(85.18,66.04) ; D43.1 33.44,60.33 v1(33.44,61.8) ; D47.1 v1(81.7,111.43) ; C765.1 v1(47.05,85.56) ; D39.1 v1(76.9,67.31) ; D42.1 v1(39.36,59.79) ; D45.1 v1(60.54,101.09) ; C771.1 v1(59.64,85.4) ; D44.1 v1(20.76,59.69)
  TOP w1.016: D36.1 v1(67.12,74.8)
  L2_GND w0.635: 71.86,77.41 J517.2 ; J517.2 71.86,75.94 ; J517.2 73.33,75.94 ; J517.2 73.33,77.41 ; 5.5,59.16 TP38.1 ; TP38.1 7.83,59.16 ; TP38.1 5.5,61.49 ; TP38.1 7.83,61.49 ; 6.73,11.2 J112.6 ; J112.6 8.35,9.59 ; J112.6 8.35,11.2 ; J112.6 6.73,9.59 ; 122.14,48.2 J97.15 ; J97.15 123.54,49.59 ; J97.15 123.54,48.2 ; J97.15 122.14,49.59 ; 114.36,85.99 U53.2 ; U53.2 116.15,84.19 ; U53.2 116.15,85.99 ; U53.2 114.36,84.19 ; J5.2 176.58,138.21 ; J5.2 175.11,136.74 ; J5.2 175.11,138.21 ; J5.2 176.58,136.74 ; 98.59,113.76 J526.2 ; J526.2 100.06,112.3 ; J526.2 100.06,113.76 ; J526.2 98.59,112.3 ; J525.2 77.25,124.95 ; J525.2 75.78,124.95 ; J525.2 77.25,126.41 ; J525.2 75.78,126.41 ; J9.2 174.16,86.19 ; J9.2 174.16,87.8 ; J9.2 172.55,87.8 ; J9.2 172.55,86.19 ; TP2.1 103.72,130.28 ; TP2.1 101.39,132.61 ; TP2.1 101.39,130.28 ; TP2.1 103.72,132.61 ; 69.43,124.95 J524.2 ; J524.2 69.43,126.41 ; J524.2 70.9,124.95 ; J524.2 70.9,126.41 ; 12.18,148.05 J85.3 ; J85.3 13.65,146.59 ; J85.3 13.65,148.05 ; J85.3 12.18,146.59 ; J43.14 86.14,13.24 ; J43.14 84.67,14.7 ; J43.14 84.67,13.24 ; J43.14 86.14,14.7 ; 148.68,35.06 J22.2 ; J522.2 38.52,38.05 ; J522.2 37.05,39.52 ; J522.2 37.05,38.05 ; J522.2 38.52,39.52 ; 69.41,24.26 J501.6 ; J501.6 69.41,22.73 ; J501.6 70.93,24.26 ; J501.6 70.93,22.73 ; J110.14 105.19,43.72 ; J110.14 105.19,45.18 ; J110.14 103.72,45.18 ; J110.14 103.72,43.72 ; J96.12 15.02,94.52 ; J96.12 15.02,95.98 ; J96.12 13.55,94.52 ; J96.12 13.55,95.98 ; 154.8,57.96 J503.1 154.8,56.34 ; J501.14 81.09,22.73 ; J501.14 79.57,24.26 ; J501.14 79.57,22.73 ; J501.14 81.09,24.26 ; J111.6 95.98,142.94 ; J111.6 95.98,144.55 ; J111.6 94.36,142.94 ; J111.6 94.36,144.55 ; J518.2 81.46,75.94 ; J518.2 81.46,77.41 ; J518.2 79.99,75.94 ; J518.2 79.99,77.41 ; J83.6 11.51,80.9 ; J83.6 8.91,83.5 ; J83.6 8.91,80.9 ; J83.6 11.51,83.5 ; J74.4 110.27,109.32 ; J74.4 108.8,109.32 ; J74.4 110.27,107.85 ; J74.4 108.8,107.85 ; 8.91,68.86 J83.5 ; J83.5 11.51,71.46 ; J83.5 8.91,71.46 ; J83.5 11.51,68.86 ; J70.9 51.88,111.25 ; J70.9 50.36,111.25 ; J70.9 50.36,109.73 ; J70.9 51.88,109.73 ; 122.09,19.59 J62.2 ; J62.2 123.56,19.59 ; J62.2 122.09,21.05 ; J62.2 123.56,21.05 ; J83.4 13.6,75.61 ; J83.4 13.6,74.25 ; J83.4 12.24,74.25 ; J83.4 12.24,75.61 ; 155.36,149.12 TP1.1 ; TP1.1 157.69,149.12 ; TP1.1 157.69,146.79 ; TP1.1 155.36,146.79 ; 16.73,61.74 J520.2 ; J520.2 18.2,60.28 ; J520.2 16.73,60.28 ; J520.2 18.2,61.74 ; 71.95,22.73 J501.8 ; J501.8 71.95,24.26 ; J501.8 73.47,24.26 ; J501.8 73.47,22.73 ; J11.2 128,76.3 ; J11.2 128,74.83 ; J11.2 126.53,74.83 ; J11.2 126.53,76.3 ; J4.2 176.58,147.54 ; J4.2 176.58,149.01 ; J4.2 175.11,147.54 ; J4.2 175.11,149.01 ; TP11.1 18.63,135.15 ; TP11.1 16.3,135.15 ; TP11.1 16.3,132.82 ; TP11.1 18.63,132.82 ; 128.14,51.59 J97.10 ; J97.10 129.54,50.2 ; J97.10 129.54,51.59 ; J97.10 128.14,50.2 ; 135.09,25.86 J121.10 ; J501.10 76.01,22.73 ; J501.10 74.49,22.73 ; J501.10 74.49,24.26 ; J501.10 76.01,24.26 ; J97.7 131.54,49.59 ; J97.7 130.14,49.59 ; J97.7 131.54,48.2 ; J97.7 130.14,48.2 ; 117.12,25.41 J120.12 117.12,26.66 ; 136.59,25.86 J121.11 ; J8.2 184.57,138.58 ; J8.2 183.1,138.58 ; J8.2 183.1,137.11 ; J8.2 184.57,137.11 ; 17.01,12.88 J104.1 15.38,12.88 ; 122.14,50.2 J97.16 ; J97.16 123.54,51.59 ; J97.16 123.54,50.2 ; J97.16 122.14,51.59 ; 166.92,7.86 167.73,7.05 ; 166.92,7.86 166.12,7.05 ; 166.92,7.86 167.73,8.66 ; 166.92,7.86 166.12,8.66 ; J2.9 85.5,147.71 ; J2.9 84.1,147.71 ; J2.9 84.1,146.1 ; J2.9 85.5,146.1 ; J516.2 58.2,81.23 ; J516.2 56.73,82.7 ; J516.2 58.2,82.7 ; J516.2 56.73,81.23 ; 104.83,85.99 U54.2 ; U54.2 106.62,84.19 ; U54.2 104.83,84.19 ; U54.2 106.62,85.99 ; 138.71,26.04 J121.12 138.71,27.3 ; 154.17,21.41 J23.1 154.17,23.04 ; J2.7 87.38,148.77 ; 66.87,22.73 J501.4 ; J501.4 66.87,24.26 ; J501.4 68.39,22.73 ; J501.4 68.39,24.26 ; TP14.1 36.41,23.6 ; TP14.1 34.08,25.93 ; TP14.1 34.08,23.6 ; TP14.1 36.41,25.93 ; 134.83,128.77 J6.10 136.08,128.77 ; 118.61,91.62 J73.1 118.61,89.99 ; 136.51,43.48 J110.1 ; J110.1 138.44,45.42 ; J110.1 136.51,45.42 ; J110.1 138.44,43.48 ; TP39.1 179.52,40.14 ; TP39.1 177.19,37.81 ; TP39.1 177.19,40.14 ; TP39.1 179.52,37.81 ; 6.25,99.49 J51.3 ; J51.3 6.25,100.96 ; J51.3 7.72,99.49 ; J51.3 7.72,100.96 ; 21.86,69.75 J521.2 ; J521.2 21.86,71.22 ; J521.2 23.33,71.22 ; J521.2 23.33,69.75 ; 115,25.22 J120.11 ; 113.5,25.22 J120.10 ; J501.16 83.63,24.26 ; J501.16 83.63,22.73 ; J501.16 82.11,24.26 ; J501.16 82.11,22.73 ; 84.65,22.73 J501.18 ; J501.18 86.17,22.73 ; J501.18 86.17,24.26 ; J501.18 84.65,24.26 ; 172.81,116.03 J506.2 ; 134.83,114.02 J6.1 136.08,114.02 ; 87.19,22.73 J501.20 ; J501.20 88.71,24.26 ; J501.20 88.71,22.73 ; J501.20 87.19,24.26 ; 77.03,24.26 J501.12 ; J501.12 77.03,22.73 ; J501.12 78.55,22.73 ; J501.12 78.55,24.26 ; 79.6,147.71 J2.8 ; J2.8 81,147.71 ; J2.8 79.6,146.1 ; 169.64,23.91 J105.1 169.64,22.28 ; 102.73,135.08 J103.1 102.73,136.7 ; 156.54,28.48 J122.7 157.79,28.48 ; 55.33,15.7 J45.2 ; 107.51,25.22 J120.6 ; 77.72,148.77 J2.6 ; 129.1,25.86 J121.6
  LY4_GND w0.635: 16.64,61.83 J520.2 ; J520.2 18.29,60.19 ; J520.2 18.29,61.83 ; J520.2 16.64,60.19 ; J97.15 123.63,49.68 ; J97.15 123.63,48.11 ; J97.15 122.05,48.11 ; J97.15 122.05,49.68 ; 8.82,80.81 J83.6 ; J83.6 11.6,83.59 ; J83.6 8.82,83.59 ; J83.6 11.6,80.81 ; J501.18 86.26,22.64 ; J501.18 84.56,22.64 ; J501.18 86.26,24.35 ; J501.18 84.56,24.35 ; J5.2 176.67,136.65 ; J5.2 175.02,136.65 ; J5.2 175.02,138.3 ; J5.2 176.67,138.3 ; 118.73,89.86 J73.1 118.73,91.75 ; 136.59,25.73 J121.11 ; 12.15,74.16 J83.4 ; J83.4 12.15,75.7 ; J83.4 13.69,74.16 ; J83.4 13.69,75.7 ; TP1.1 157.78,146.7 ; TP1.1 155.27,146.7 ; TP1.1 157.78,149.21 ; TP1.1 155.27,149.21 ; J4.2 176.67,149.1 ; J4.2 176.67,147.45 ; J4.2 175.02,149.1 ; J4.2 175.02,147.45 ; 79.47,145.97 J2.8 ; J2.8 81.13,147.83 ; J2.8 79.47,147.83 ; 136.17,113.93 J6.1 134.74,113.93 ; 98.5,112.21 J526.2 ; J526.2 100.15,112.21 ; J526.2 98.5,113.85 ; J526.2 100.15,113.85 ; 156.45,28.39 J122.7 157.88,28.39 ; J97.7 131.63,48.11 ; J97.7 131.63,49.68 ; J97.7 130.05,49.68 ; J97.7 130.05,48.11 ; J74.4 110.36,109.41 ; J74.4 110.36,107.76 ; J74.4 108.71,109.41 ; J74.4 108.71,107.76 ; 17.13,13.01 J104.1 15.25,13.01 ; J501.12 78.64,22.64 ; J501.12 76.94,22.64 ; J501.12 78.64,24.35 ; J501.12 76.94,24.35 ; 166.03,6.96 166.92,7.86 ; 166.92,7.86 167.82,6.96 ; 166.92,7.86 167.82,8.75 ; 166.92,7.86 166.03,8.75 ; J516.2 58.29,81.14 ; J516.2 58.29,82.79 ; J516.2 56.64,82.79 ; J516.2 56.64,81.14 ; 169.77,24.04 J105.1 169.77,22.16 ; J97.16 123.63,50.11 ; J97.16 122.05,51.68 ; J97.16 122.05,50.11 ; J97.16 123.63,51.68 ; TP2.1 103.81,130.19 ; TP2.1 101.3,130.19 ; TP2.1 103.81,132.7 ; TP2.1 101.3,132.7 ; 6.16,101.05 J51.3 ; J51.3 7.81,101.05 ; J51.3 7.81,99.4 ; J51.3 6.16,99.4 ; J522.2 38.61,39.61 ; J522.2 36.96,39.61 ; J522.2 38.61,37.96 ; J522.2 36.96,37.96 ; J62.2 123.65,21.14 ; J62.2 122,21.14 ; J62.2 123.65,19.5 ; J62.2 122,19.5 ; 128.05,50.11 J97.10 ; J97.10 129.63,51.68 ; J97.10 128.05,51.68 ; J97.10 129.63,50.11 ; J501.16 83.72,22.64 ; J501.16 83.72,24.35 ; J501.16 82.02,22.64 ; J501.16 82.02,24.35 ; J518.2 81.55,77.5 ; J518.2 79.9,77.5 ; J518.2 81.55,75.85 ; J518.2 79.9,75.85 ; 66.78,22.64 J501.4 ; J501.4 68.48,22.64 ; J501.4 68.48,24.35 ; J501.4 66.78,24.35 ; J524.2 70.99,126.5 ; J524.2 69.34,126.5 ; J524.2 69.34,124.86 ; J524.2 70.99,124.86 ; 126.44,74.74 J11.2 ; J11.2 126.44,76.39 ; J11.2 128.09,76.39 ; J11.2 128.09,74.74 ; 117.21,26.75 J120.12 117.21,25.32 ; J517.2 73.42,75.85 ; J517.2 73.42,77.5 ; J517.2 71.77,77.5 ; J517.2 71.77,75.85 ; 103.63,45.27 J110.14 ; J110.14 105.28,45.27 ; J110.14 105.28,43.63 ; J110.14 103.63,43.63 ; 134.74,128.86 J6.10 136.17,128.86 ; 16.21,132.73 TP11.1 ; TP11.1 18.72,135.24 ; TP11.1 16.21,135.24 ; TP11.1 18.72,132.73 ; J112.6 8.44,11.29 ; J112.6 8.44,9.5 ; J112.6 6.64,11.29 ; J112.6 6.64,9.5 ; 71.86,24.35 J501.8 ; J501.8 71.86,22.64 ; J501.8 73.56,24.35 ; J501.8 73.56,22.64 ; J501.20 88.8,24.35 ; J501.20 87.1,22.64 ; J501.20 88.8,22.64 ; J501.20 87.1,24.35 ; TP14.1 36.5,23.51 ; TP14.1 33.99,23.51 ; TP14.1 36.5,26.02 ; TP14.1 33.99,26.02 ; 138.8,27.39 J121.12 138.8,25.95 ; 79.48,24.35 J501.14 ; J501.14 81.18,22.64 ; J501.14 81.18,24.35 ; J501.14 79.48,22.64 ; J501.10 76.1,22.64 ; J501.10 74.4,24.35 ; J501.10 74.4,22.64 ; J501.10 76.1,24.35 ; J96.12 15.11,94.43 ; J96.12 15.11,96.07 ; J96.12 13.46,94.43 ; TP38.1 7.92,59.07 ; TP38.1 7.92,61.58 ; TP38.1 5.41,61.58 ; TP38.1 5.41,59.07 ; J85.3 13.74,146.5 ; J85.3 12.09,148.14 ; J85.3 12.09,146.5 ; J85.3 13.74,148.14 ; 84.58,13.15 J43.14 ; J43.14 86.23,14.79 ; J43.14 84.58,14.79 ; J43.14 86.23,13.15 ; 104.74,84.1 U54.2 ; U54.2 106.71,86.08 ; U54.2 106.71,84.1 ; U54.2 104.74,86.08 ; J521.2 23.42,69.66 ; J521.2 21.77,69.66 ; J521.2 21.77,71.31 ; J521.2 23.42,71.31 ; 83.97,145.97 J2.9 ; J2.9 83.97,147.83 ; J2.9 85.63,145.97 ; J2.9 85.63,147.83 ; 102.86,134.95 J103.1 102.86,136.83 ; J83.5 11.6,71.55 ; J83.5 11.6,68.77 ; J83.5 8.82,68.77 ; J83.5 8.82,71.55 ; 69.32,22.64 J501.6 ; J501.6 69.32,24.35 ; J501.6 71.02,22.64 ; J501.6 71.02,24.35 ; J525.2 77.34,124.86 ; J525.2 77.34,126.5 ; J525.2 75.69,126.5 ; J525.2 75.69,124.86 ; J111.6 96.07,142.85 ; J111.6 94.27,142.85 ; J111.6 94.27,144.64 ; J111.6 96.07,144.64 ; 107.51,25.09 J120.6 ; J2.7 87.48,148.65 ; J9.2 174.25,87.89 ; J9.2 174.25,86.1 ; J9.2 172.46,86.1 ; J9.2 172.46,87.89 ; 154.29,21.28 J23.1 154.29,23.17 ; J110.1 138.57,45.54 ; J110.1 136.38,43.36 ; J110.1 136.38,45.54 ; J110.1 138.57,43.36 ; J70.9 51.97,109.64 ; J70.9 51.97,111.34 ; J70.9 50.27,109.64 ; J70.9 50.27,111.34 ; J8.2 184.66,138.67 ; J8.2 183.01,138.67 ; J8.2 183.01,137.02 ; J8.2 184.66,137.02 ; 154.93,56.21 J503.1 154.93,58.09 ; 55.33,15.57 J45.2 ; 114.27,84.1 U53.2 ; U53.2 116.24,86.08 ; U53.2 114.27,86.08 ; U53.2 116.24,84.1 ; TP39.1 179.61,40.23 ; TP39.1 177.1,40.23 ; TP39.1 179.61,37.72 ; TP39.1 177.1,37.72 ; 115,25.09 J120.11 ; 172.81,115.9 J506.2 ; 113.5,25.09 J120.10 ; 148.68,34.94 J22.2 ; 77.62,148.65 J2.6 ; 135.09,25.73 J121.10 ; 129.1,25.73 J121.6
  LY6_GND w0.635: J2.9 85.63,145.97 ; J2.9 85.63,147.83 ; J2.9 83.97,147.83 ; J2.9 83.97,145.97 ; 16.64,60.19 J520.2 ; J520.2 18.29,60.19 ; J520.2 16.64,61.83 ; J520.2 18.29,61.83 ; J85.3 13.74,148.14 ; J85.3 13.74,146.5 ; J85.3 12.09,146.5 ; J85.3 12.09,148.14 ; 8.82,71.55 J83.5 ; J83.5 11.6,71.55 ; J83.5 11.6,68.77 ; J83.5 8.82,68.77 ; 79.48,22.64 J501.14 ; J501.14 81.18,24.35 ; J501.14 81.18,22.64 ; J501.14 79.48,24.35 ; 56.64,81.14 J516.2 ; J516.2 58.29,82.79 ; J516.2 56.64,82.79 ; J516.2 58.29,81.14 ; 101.3,130.19 TP2.1 ; TP2.1 103.81,132.7 ; TP2.1 101.3,132.7 ; TP2.1 103.81,130.19 ; 122,21.14 J62.2 ; J62.2 122,19.5 ; J62.2 123.65,19.5 ; J62.2 123.65,21.14 ; 154.29,21.28 J23.1 154.29,23.17 ; J501.8 73.56,22.64 ; J501.8 73.56,24.35 ; J501.8 71.86,22.64 ; J501.8 71.86,24.35 ; J83.4 13.69,74.16 ; J83.4 12.15,74.16 ; J83.4 13.69,75.7 ; J83.4 12.15,75.7 ; J97.16 123.63,50.11 ; J97.16 122.05,51.68 ; J97.16 122.05,50.11 ; J97.16 123.63,51.68 ; 135.09,25.73 J121.10 ; J97.15 123.63,48.11 ; J97.15 123.63,49.68 ; J97.15 122.05,49.68 ; J97.15 122.05,48.11 ; 69.32,24.35 J501.6 ; J501.6 71.02,24.35 ; J501.6 71.02,22.64 ; J501.6 69.32,22.64 ; J96.12 15.11,96.07 ; J96.12 13.46,94.43 ; J96.12 15.11,94.43 ; 169.77,24.04 J105.1 169.77,22.16 ; 104.74,86.08 U54.2 ; U54.2 104.74,84.1 ; U54.2 106.71,86.08 ; U54.2 106.71,84.1 ; 134.74,113.93 J6.1 136.17,113.93 ; 50.27,111.34 J70.9 ; J70.9 50.27,109.64 ; J70.9 51.97,109.64 ; J70.9 51.97,111.34 ; 84.56,24.35 J501.18 ; J501.18 86.26,24.35 ; J501.18 86.26,22.64 ; J501.18 84.56,22.64 ; 113.5,25.09 J120.10 ; 75.69,124.86 J525.2 ; J525.2 77.34,126.5 ; J525.2 75.69,126.5 ; J525.2 77.34,124.86 ; 79.47,147.83 J2.8 ; J2.8 79.47,145.97 ; J2.8 81.13,147.83 ; 128.05,51.68 J97.10 ; J97.10 129.63,50.11 ; J97.10 128.05,50.11 ; J97.10 129.63,51.68 ; J112.6 8.44,11.29 ; J112.6 6.64,9.5 ; J112.6 6.64,11.29 ; J112.6 8.44,9.5 ; 71.77,75.85 J517.2 ; J517.2 73.42,77.5 ; J517.2 73.42,75.85 ; J517.2 71.77,77.5 ; J11.2 128.09,74.74 ; J11.2 126.44,74.74 ; J11.2 128.09,76.39 ; J11.2 126.44,76.39 ; 66.78,22.64 J501.4 ; J501.4 66.78,24.35 ; J501.4 68.48,22.64 ; J501.4 68.48,24.35 ; J522.2 38.61,37.96 ; J522.2 36.96,39.61 ; J522.2 36.96,37.96 ; J522.2 38.61,39.61 ; J74.4 110.36,107.76 ; J74.4 110.36,109.41 ; J74.4 108.71,109.41 ; J74.4 108.71,107.76 ; 74.4,24.35 J501.10 ; J501.10 76.1,22.64 ; J501.10 74.4,22.64 ; J501.10 76.1,24.35 ; J43.14 86.23,14.79 ; J43.14 86.23,13.15 ; J43.14 84.58,14.79 ; J43.14 84.58,13.15 ; 177.1,37.72 TP39.1 ; TP39.1 179.61,40.23 ; TP39.1 179.61,37.72 ; TP39.1 177.1,40.23 ; J8.2 184.66,138.67 ; J8.2 184.66,137.02 ; J8.2 183.01,138.67 ; J8.2 183.01,137.02 ; 115,25.09 J120.11 ; 172.46,86.1 J9.2 ; J9.2 174.25,86.1 ; J9.2 172.46,87.89 ; J9.2 174.25,87.89 ; J97.7 131.63,48.11 ; J97.7 130.05,48.11 ; J97.7 131.63,49.68 ; J97.7 130.05,49.68 ; 175.02,138.3 J5.2 ; J5.2 175.02,136.65 ; J5.2 176.67,138.3 ; J5.2 176.67,136.65 ; J110.1 138.57,43.36 ; J110.1 136.38,45.54 ; J110.1 136.38,43.36 ; J110.1 138.57,45.54 ; 166.92,7.86 167.82,6.96 ; 166.92,7.86 166.03,8.75 ; 166.92,7.86 166.03,6.96 ; 166.92,7.86 167.82,8.75 ; 114.27,86.08 U53.2 ; U53.2 116.24,84.1 ; U53.2 116.24,86.08 ; U53.2 114.27,84.1 ; 79.9,75.85 J518.2 ; J518.2 81.55,75.85 ; J518.2 81.55,77.5 ; J518.2 79.9,77.5 ; 154.93,56.21 J503.1 154.93,58.09 ; 156.45,28.39 J122.7 157.88,28.39 ; 118.73,89.86 J73.1 118.73,91.75 ; 136.17,128.86 J6.10 134.74,128.86 ; 5.41,61.58 TP38.1 ; TP38.1 7.92,59.07 ; TP38.1 5.41,59.07 ; TP38.1 7.92,61.58 ; 55.33,15.57 J45.2 ; 98.5,113.85 J526.2 ; J526.2 100.15,113.85 ; J526.2 100.15,112.21 ; J526.2 98.5,112.21 ; J501.20 88.8,22.64 ; J501.20 87.1,22.64 ; J501.20 87.1,24.35 ; J501.20 88.8,24.35 ; 94.27,142.85 J111.6 ; J111.6 96.07,142.85 ; J111.6 96.07,144.64 ; J111.6 94.27,144.64 ; TP11.1 18.72,135.24 ; TP11.1 16.21,135.24 ; TP11.1 16.21,132.73 ; TP11.1 18.72,132.73 ; J501.12 78.64,24.35 ; J501.12 76.94,24.35 ; J501.12 76.94,22.64 ; J501.12 78.64,22.64 ; J51.3 7.81,101.05 ; J51.3 6.16,99.4 ; J51.3 6.16,101.05 ; J51.3 7.81,99.4 ; 33.99,23.51 TP14.1 ; TP14.1 36.5,23.51 ; TP14.1 36.5,26.02 ; TP14.1 33.99,26.02 ; J83.6 11.6,80.81 ; J83.6 11.6,83.59 ; J83.6 8.82,83.59 ; J83.6 8.82,80.81 ; TP1.1 157.78,149.21 ; TP1.1 155.27,149.21 ; TP1.1 155.27,146.7 ; TP1.1 157.78,146.7 ; J501.16 83.72,24.35 ; J501.16 82.02,24.35 ; J501.16 83.72,22.64 ; J501.16 82.02,22.64 ; 136.59,25.73 J121.11 ; 175.02,147.45 J4.2 ; J4.2 176.67,147.45 ; J4.2 175.02,149.1 ; J4.2 176.67,149.1 ; 138.8,27.39 J121.12 138.8,25.95 ; 21.77,71.31 J521.2 ; J521.2 21.77,69.66 ; J521.2 23.42,71.31 ; J521.2 23.42,69.66 ; 117.21,26.75 J120.12 117.21,25.32 ; 102.86,134.95 J103.1 102.86,136.83 ; 107.51,25.09 J120.6 ; 103.63,43.63 J110.14 ; J110.14 103.63,45.27 ; J110.14 105.28,43.63 ; J110.14 105.28,45.27 ; 69.34,124.86 J524.2 ; J524.2 70.99,126.5 ; J524.2 70.99,124.86 ; J524.2 69.34,126.5 ; 15.25,13.01 J104.1 17.13,13.01 ; J2.7 87.48,148.65 ; 129.1,25.73 J121.6 ; 148.68,34.94 J22.2 ; 77.62,148.65 J2.6 ; 172.81,115.9 J506.2
  LY9_GND w0.635: 155.27,146.7 TP1.1 ; TP1.1 157.78,146.7 ; TP1.1 155.27,149.21 ; TP1.1 157.78,149.21 ; 16.64,61.83 J520.2 ; J520.2 18.29,60.19 ; J520.2 16.64,60.19 ; J520.2 18.29,61.83 ; 126.44,74.74 J11.2 ; J11.2 126.44,76.39 ; J11.2 128.09,74.74 ; J11.2 128.09,76.39 ; 169.77,24.04 J105.1 169.77,22.16 ; J97.7 131.63,48.11 ; J97.7 130.05,48.11 ; J97.7 130.05,49.68 ; J97.7 131.63,49.68 ; 118.73,89.86 J73.1 118.73,91.75 ; 83.97,145.97 J2.9 ; J2.9 85.63,147.83 ; J2.9 85.63,145.97 ; J2.9 83.97,147.83 ; 6.64,11.29 J112.6 ; J112.6 6.64,9.5 ; J112.6 8.44,9.5 ; J112.6 8.44,11.29 ; J85.3 13.74,148.14 ; J85.3 12.09,148.14 ; J85.3 12.09,146.5 ; J85.3 13.74,146.5 ; 154.93,56.21 J503.1 154.93,58.09 ; 84.56,22.64 J501.18 ; J501.18 86.26,22.64 ; J501.18 86.26,24.35 ; J501.18 84.56,24.35 ; 8.82,80.81 J83.6 ; J83.6 11.6,83.59 ; J83.6 8.82,83.59 ; J83.6 11.6,80.81 ; J8.2 184.66,138.67 ; J8.2 184.66,137.02 ; J8.2 183.01,137.02 ; J8.2 183.01,138.67 ; J110.1 138.57,45.54 ; J110.1 136.38,45.54 ; J110.1 136.38,43.36 ; J110.1 138.57,43.36 ; 122,21.14 J62.2 ; J62.2 123.65,19.5 ; J62.2 123.65,21.14 ; J62.2 122,19.5 ; 122.05,50.11 J97.16 ; J97.16 122.05,51.68 ; J97.16 123.63,50.11 ; J97.16 123.63,51.68 ; 94.27,142.85 J111.6 ; J111.6 94.27,144.64 ; J111.6 96.07,142.85 ; J111.6 96.07,144.64 ; 84.58,13.15 J43.14 ; J43.14 84.58,14.79 ; J43.14 86.23,13.15 ; J43.14 86.23,14.79 ; 175.02,136.65 J5.2 ; J5.2 176.67,136.65 ; J5.2 176.67,138.3 ; J5.2 175.02,138.3 ; 136.59,25.73 J121.11 ; 79.9,75.85 J518.2 ; J518.2 81.55,77.5 ; J518.2 81.55,75.85 ; J518.2 79.9,77.5 ; 157.88,28.39 J122.7 156.45,28.39 ; J501.8 73.56,24.35 ; J501.8 71.86,24.35 ; J501.8 73.56,22.64 ; J501.8 71.86,22.64 ; 166.03,8.75 166.92,7.86 ; 166.92,7.86 166.03,6.96 ; 166.92,7.86 167.82,8.75 ; 166.92,7.86 167.82,6.96 ; 114.27,84.1 U53.2 ; U53.2 116.24,86.08 ; U53.2 116.24,84.1 ; U53.2 114.27,86.08 ; 103.63,43.63 J110.14 ; J110.14 103.63,45.27 ; J110.14 105.28,43.63 ; J110.14 105.28,45.27 ; 71.77,75.85 J517.2 ; J517.2 73.42,77.5 ; J517.2 73.42,75.85 ; J517.2 71.77,77.5 ; 117.21,26.75 J120.12 117.21,25.32 ; TP11.1 18.72,132.73 ; TP11.1 16.21,132.73 ; TP11.1 16.21,135.24 ; TP11.1 18.72,135.24 ; J97.10 129.63,50.11 ; J97.10 129.63,51.68 ; J97.10 128.05,50.11 ; J97.10 128.05,51.68 ; 136.17,128.86 J6.10 134.74,128.86 ; J51.3 7.81,99.4 ; J51.3 6.16,99.4 ; J51.3 6.16,101.05 ; J51.3 7.81,101.05 ; 177.1,40.23 TP39.1 ; TP39.1 177.1,37.72 ; TP39.1 179.61,40.23 ; TP39.1 179.61,37.72 ; J501.14 81.18,22.64 ; J501.14 79.48,24.35 ; J501.14 79.48,22.64 ; J501.14 81.18,24.35 ; J525.2 77.34,126.5 ; J525.2 77.34,124.86 ; J525.2 75.69,126.5 ; J525.2 75.69,124.86 ; 129.1,25.73 J121.6 ; 12.15,75.7 J83.4 ; J83.4 13.69,75.7 ; J83.4 13.69,74.16 ; J83.4 12.15,74.16 ; J74.4 110.36,109.41 ; J74.4 108.71,107.76 ; J74.4 108.71,109.41 ; J74.4 110.36,107.76 ; J70.9 51.97,109.64 ; J70.9 51.97,111.34 ; J70.9 50.27,109.64 ; J70.9 50.27,111.34 ; J83.5 11.6,71.55 ; J83.5 8.82,68.77 ; J83.5 8.82,71.55 ; J83.5 11.6,68.77 ; 77.62,148.65 J2.6 ; 87.1,22.64 J501.20 ; J501.20 87.1,24.35 ; J501.20 88.8,22.64 ; J501.20 88.8,24.35 ; 66.78,22.64 J501.4 ; J501.4 66.78,24.35 ; J501.4 68.48,24.35 ; J501.4 68.48,22.64 ; 82.02,24.35 J501.16 ; J501.16 83.72,24.35 ; J501.16 82.02,22.64 ; J501.16 83.72,22.64 ; TP2.1 103.81,130.19 ; TP2.1 101.3,130.19 ; TP2.1 103.81,132.7 ; TP2.1 101.3,132.7 ; 56.64,81.14 J516.2 ; J516.2 58.29,81.14 ; J516.2 56.64,82.79 ; J516.2 58.29,82.79 ; 172.46,86.1 J9.2 ; J9.2 174.25,86.1 ; J9.2 172.46,87.89 ; J9.2 174.25,87.89 ; 13.46,94.43 J96.12 ; J96.12 15.11,94.43 ; J96.12 15.11,96.07 ; 21.77,71.31 J521.2 ; J521.2 23.42,71.31 ; J521.2 23.42,69.66 ; J521.2 21.77,69.66 ; J524.2 70.99,126.5 ; J524.2 69.34,126.5 ; J524.2 69.34,124.86 ; J524.2 70.99,124.86 ; 79.47,145.97 J2.8 ; J2.8 79.47,147.83 ; J2.8 81.13,147.83 ; J501.12 78.64,24.35 ; J501.12 78.64,22.64 ; J501.12 76.94,24.35 ; J501.12 76.94,22.64 ; 138.8,27.39 J121.12 138.8,25.95 ; 69.32,22.64 J501.6 ; J501.6 71.02,24.35 ; J501.6 69.32,24.35 ; J501.6 71.02,22.64 ; J526.2 100.15,113.85 ; J526.2 100.15,112.21 ; J526.2 98.5,113.85 ; J526.2 98.5,112.21 ; 113.5,25.09 J120.10 ; 154.29,23.17 J23.1 154.29,21.28 ; 33.99,26.02 TP14.1 ; TP14.1 36.5,26.02 ; TP14.1 36.5,23.51 ; TP14.1 33.99,23.51 ; 74.4,24.35 J501.10 ; J501.10 76.1,22.64 ; J501.10 74.4,22.64 ; J501.10 76.1,24.35 ; U54.2 106.71,84.1 ; U54.2 106.71,86.08 ; U54.2 104.74,86.08 ; U54.2 104.74,84.1 ; 17.13,13.01 J104.1 15.25,13.01 ; J97.15 123.63,49.68 ; J97.15 123.63,48.11 ; J97.15 122.05,48.11 ; J97.15 122.05,49.68 ; J2.7 87.48,148.65 ; J4.2 176.67,149.1 ; J4.2 175.02,147.45 ; J4.2 175.02,149.1 ; J4.2 176.67,147.45 ; 102.86,134.95 J103.1 102.86,136.83 ; TP38.1 7.92,61.58 ; TP38.1 5.41,59.07 ; TP38.1 5.41,61.58 ; TP38.1 7.92,59.07 ; 55.33,15.57 J45.2 ; 135.09,25.73 J121.10 ; 36.96,37.96 J522.2 ; J522.2 38.61,37.96 ; J522.2 38.61,39.61 ; J522.2 36.96,39.61 ; 115,25.09 J120.11 ; 134.74,113.93 J6.1 136.17,113.93 ; 107.51,25.09 J120.6 ; 172.81,115.9 J506.2 ; 148.68,34.94 J22.2
  LY11_GND w0.635: J501.6 71.02,24.35 ; J501.6 69.32,22.64 ; J501.6 71.02,22.64 ; J501.6 69.32,24.35 ; J501.18 86.26,24.35 ; J501.18 84.56,22.64 ; J501.18 84.56,24.35 ; J501.18 86.26,22.64 ; U54.2 106.71,86.08 ; U54.2 106.71,84.1 ; U54.2 104.74,86.08 ; U54.2 104.74,84.1 ; J9.2 174.25,86.1 ; J9.2 172.46,87.89 ; J9.2 172.46,86.1 ; J9.2 174.25,87.89 ; 155.27,146.7 TP1.1 ; TP1.1 155.27,149.21 ; TP1.1 157.78,146.7 ; TP1.1 157.78,149.21 ; 177.1,40.23 TP39.1 ; TP39.1 177.1,37.72 ; TP39.1 179.61,37.72 ; TP39.1 179.61,40.23 ; J97.7 131.63,48.11 ; J97.7 130.05,49.68 ; J97.7 131.63,49.68 ; J97.7 130.05,48.11 ; J2.7 87.48,148.65 ; 17.13,13.01 J104.1 15.25,13.01 ; 114.27,84.1 U53.2 ; U53.2 116.24,84.1 ; U53.2 114.27,86.08 ; U53.2 116.24,86.08 ; 71.77,77.5 J517.2 ; J517.2 73.42,75.85 ; J517.2 71.77,75.85 ; J517.2 73.42,77.5 ; 122,19.5 J62.2 ; J62.2 123.65,21.14 ; J62.2 123.65,19.5 ; J62.2 122,21.14 ; J518.2 81.55,75.85 ; J518.2 79.9,77.5 ; J518.2 79.9,75.85 ; J518.2 81.55,77.5 ; J2.9 85.63,145.97 ; J2.9 85.63,147.83 ; J2.9 83.97,147.83 ; J2.9 83.97,145.97 ; J96.12 15.11,96.07 ; J96.12 15.11,94.43 ; J96.12 13.46,94.43 ; 12.09,148.14 J85.3 ; J85.3 12.09,146.5 ; J85.3 13.74,148.14 ; J85.3 13.74,146.5 ; J97.15 123.63,49.68 ; J97.15 122.05,48.11 ; J97.15 123.63,48.11 ; J97.15 122.05,49.68 ; J97.16 123.63,51.68 ; J97.16 122.05,50.11 ; J97.16 123.63,50.11 ; J97.16 122.05,51.68 ; 154.29,23.17 J23.1 154.29,21.28 ; 101.3,130.19 TP2.1 ; TP2.1 101.3,132.7 ; TP2.1 103.81,130.19 ; TP2.1 103.81,132.7 ; 138.8,27.39 J121.12 138.8,25.95 ; 136.59,25.73 J121.11 ; J74.4 110.36,107.76 ; J74.4 108.71,109.41 ; J74.4 110.36,109.41 ; J74.4 108.71,107.76 ; J11.2 128.09,74.74 ; J11.2 128.09,76.39 ; J11.2 126.44,74.74 ; J11.2 126.44,76.39 ; 117.21,26.75 J120.12 117.21,25.32 ; 50.27,109.64 J70.9 ; J70.9 51.97,111.34 ; J70.9 50.27,111.34 ; J70.9 51.97,109.64 ; J521.2 23.42,69.66 ; J521.2 21.77,71.31 ; J521.2 23.42,71.31 ; J521.2 21.77,69.66 ; 8.82,71.55 J83.5 ; J83.5 11.6,71.55 ; J83.5 11.6,68.77 ; J83.5 8.82,68.77 ; J516.2 58.29,81.14 ; J516.2 56.64,81.14 ; J516.2 56.64,82.79 ; J516.2 58.29,82.79 ; 128.05,51.68 J97.10 ; J97.10 129.63,51.68 ; J97.10 128.05,50.11 ; J97.10 129.63,50.11 ; J51.3 7.81,99.4 ; J51.3 7.81,101.05 ; J51.3 6.16,99.4 ; J51.3 6.16,101.05 ; 102.86,134.95 J103.1 102.86,136.83 ; J112.6 8.44,11.29 ; J112.6 6.64,9.5 ; J112.6 6.64,11.29 ; J112.6 8.44,9.5 ; 98.5,113.85 J526.2 ; J526.2 98.5,112.21 ; J526.2 100.15,112.21 ; J526.2 100.15,113.85 ; 118.73,91.75 J73.1 118.73,89.86 ; J501.12 78.64,22.64 ; J501.12 78.64,24.35 ; J501.12 76.94,24.35 ; J501.12 76.94,22.64 ; J110.14 105.28,45.27 ; J110.14 103.63,45.27 ; J110.14 103.63,43.63 ; J110.14 105.28,43.63 ; 169.77,22.16 J105.1 169.77,24.04 ; J501.8 73.56,24.35 ; J501.8 71.86,22.64 ; J501.8 73.56,22.64 ; J501.8 71.86,24.35 ; J4.2 176.67,149.1 ; J4.2 175.02,147.45 ; J4.2 176.67,147.45 ; J4.2 175.02,149.1 ; 129.1,25.73 J121.6 ; 166.92,7.86 167.82,6.96 ; 166.92,7.86 166.03,6.96 ; 166.92,7.86 166.03,8.75 ; 166.92,7.86 167.82,8.75 ; TP14.1 36.5,23.51 ; TP14.1 33.99,26.02 ; TP14.1 33.99,23.51 ; TP14.1 36.5,26.02 ; J501.4 68.48,22.64 ; J501.4 66.78,24.35 ; J501.4 68.48,24.35 ; J501.4 66.78,22.64 ; J501.14 81.18,24.35 ; J501.14 79.48,22.64 ; J501.14 79.48,24.35 ; J501.14 81.18,22.64 ; 135.09,25.73 J121.10 ; 154.93,56.21 J503.1 154.93,58.09 ; 82.02,24.35 J501.16 ; J501.16 83.72,22.64 ; J501.16 83.72,24.35 ; J501.16 82.02,22.64 ; 16.64,60.19 J520.2 ; J520.2 18.29,61.83 ; J520.2 18.29,60.19 ; J520.2 16.64,61.83 ; 113.5,25.09 J120.10 ; 107.51,25.09 J120.6 ; 69.34,124.86 J524.2 ; J524.2 70.99,124.86 ; J524.2 70.99,126.5 ; J524.2 69.34,126.5 ; 134.74,113.93 J6.1 136.17,113.93 ; J522.2 38.61,37.96 ; J522.2 38.61,39.61 ; J522.2 36.96,39.61 ; J522.2 36.96,37.96 ; J110.1 138.57,45.54 ; J110.1 138.57,43.36 ; J110.1 136.38,45.54 ; J110.1 136.38,43.36 ; TP38.1 7.92,61.58 ; TP38.1 7.92,59.07 ; TP38.1 5.41,61.58 ; TP38.1 5.41,59.07 ; 175.02,136.65 J5.2 ; J5.2 176.67,138.3 ; J5.2 175.02,138.3 ; J5.2 176.67,136.65 ; 55.33,15.57 J45.2 ; 79.47,145.97 J2.8 ; J2.8 79.47,147.83 ; J2.8 81.13,147.83 ; J43.14 86.23,14.79 ; J43.14 86.23,13.15 ; J43.14 84.58,14.79 ; J43.14 84.58,13.15 ; 115,25.09 J120.11 ; 87.1,22.64 J501.20 ; J501.20 88.8,22.64 ; J501.20 87.1,24.35 ; J501.20 88.8,24.35 ; 75.69,126.5 J525.2 ; J525.2 77.34,126.5 ; J525.2 75.69,124.86 ; J525.2 77.34,124.86 ; J111.6 96.07,144.64 ; J111.6 94.27,144.64 ; J111.6 94.27,142.85 ; J111.6 96.07,142.85 ; 136.17,128.86 J6.10 134.74,128.86 ; TP11.1 18.72,132.73 ; TP11.1 16.21,135.24 ; TP11.1 16.21,132.73 ; TP11.1 18.72,135.24 ; J83.6 11.6,83.59 ; J83.6 11.6,80.81 ; J83.6 8.82,80.81 ; J83.6 8.82,83.59 ; J83.4 13.69,75.7 ; J83.4 13.69,74.16 ; J83.4 12.15,74.16 ; J83.4 12.15,75.7 ; 157.88,28.39 J122.7 156.45,28.39 ; 172.81,115.9 J506.2 ; 183.01,137.02 J8.2 ; J8.2 184.66,137.02 ; J8.2 183.01,138.67 ; J8.2 184.66,138.67 ; J501.10 76.1,22.64 ; J501.10 74.4,22.64 ; J501.10 76.1,24.35 ; J501.10 74.4,24.35 ; 77.62,148.65 J2.6 ; 148.68,34.94 J22.2
  L13_GND w0.635: TP14.1 36.5,23.51 ; TP14.1 33.99,23.51 ; TP14.1 33.99,26.02 ; TP14.1 36.5,26.02 ; 175.02,149.1 J4.2 ; J4.2 176.67,149.1 ; J4.2 175.02,147.45 ; J4.2 176.67,147.45 ; J501.12 78.64,22.64 ; J501.12 76.94,24.35 ; J501.12 76.94,22.64 ; J501.12 78.64,24.35 ; 50.27,109.64 J70.9 ; J70.9 51.97,111.34 ; J70.9 50.27,111.34 ; J70.9 51.97,109.64 ; J8.2 184.66,138.67 ; J8.2 183.01,137.02 ; J8.2 184.66,137.02 ; J8.2 183.01,138.67 ; J83.5 11.6,71.55 ; J83.5 8.82,71.55 ; J83.5 11.6,68.77 ; J83.5 8.82,68.77 ; J11.2 128.09,74.74 ; J11.2 126.44,76.39 ; J11.2 128.09,76.39 ; J11.2 126.44,74.74 ; 114.27,84.1 U53.2 ; U53.2 116.24,86.08 ; U53.2 114.27,86.08 ; U53.2 116.24,84.1 ; 15.25,13.01 J104.1 17.13,13.01 ; J51.3 7.81,99.4 ; J51.3 6.16,101.05 ; J51.3 6.16,99.4 ; J51.3 7.81,101.05 ; J62.2 123.65,21.14 ; J62.2 123.65,19.5 ; J62.2 122,21.14 ; J62.2 122,19.5 ; J96.12 15.11,96.07 ; J96.12 13.46,94.43 ; J96.12 15.11,94.43 ; 79.9,77.5 J518.2 ; J518.2 81.55,77.5 ; J518.2 79.9,75.85 ; J518.2 81.55,75.85 ; 84.56,24.35 J501.18 ; J501.18 86.26,22.64 ; J501.18 84.56,22.64 ; J501.18 86.26,24.35 ; 75.69,124.86 J525.2 ; J525.2 77.34,126.5 ; J525.2 75.69,126.5 ; J525.2 77.34,124.86 ; 118.73,91.75 J73.1 118.73,89.86 ; 16.64,61.83 J520.2 ; J520.2 18.29,61.83 ; J520.2 18.29,60.19 ; J520.2 16.64,60.19 ; 66.78,22.64 J501.4 ; J501.4 68.48,22.64 ; J501.4 68.48,24.35 ; J501.4 66.78,24.35 ; 177.1,37.72 TP39.1 ; TP39.1 179.61,37.72 ; TP39.1 177.1,40.23 ; TP39.1 179.61,40.23 ; 87.1,22.64 J501.20 ; J501.20 88.8,22.64 ; J501.20 88.8,24.35 ; J501.20 87.1,24.35 ; 148.68,34.94 J22.2 ; 155.27,146.7 TP1.1 ; TP1.1 157.78,149.21 ; TP1.1 157.78,146.7 ; TP1.1 155.27,149.21 ; J43.14 86.23,13.15 ; J43.14 86.23,14.79 ; J43.14 84.58,13.15 ; J43.14 84.58,14.79 ; 107.51,25.09 J120.6 ; J501.14 81.18,22.64 ; J501.14 79.48,24.35 ; J501.14 81.18,24.35 ; J501.14 79.48,22.64 ; U54.2 106.71,86.08 ; U54.2 104.74,84.1 ; U54.2 106.71,84.1 ; U54.2 104.74,86.08 ; TP38.1 7.92,59.07 ; TP38.1 5.41,61.58 ; TP38.1 5.41,59.07 ; TP38.1 7.92,61.58 ; 101.3,130.19 TP2.1 ; TP2.1 101.3,132.7 ; TP2.1 103.81,130.19 ; TP2.1 103.81,132.7 ; 135.09,25.73 J121.10 ; 169.77,22.16 J105.1 169.77,24.04 ; 98.5,113.85 J526.2 ; J526.2 100.15,113.85 ; J526.2 100.15,112.21 ; J526.2 98.5,112.21 ; 69.32,24.35 J501.6 ; J501.6 69.32,22.64 ; J501.6 71.02,22.64 ; J501.6 71.02,24.35 ; 134.74,128.86 J6.10 136.17,128.86 ; J501.16 83.72,24.35 ; J501.16 83.72,22.64 ; J501.16 82.02,22.64 ; J501.16 82.02,24.35 ; 130.05,48.11 J97.7 ; J97.7 131.63,49.68 ; J97.7 131.63,48.11 ; J97.7 130.05,49.68 ; J2.7 87.48,148.65 ; 12.15,75.7 J83.4 ; J83.4 13.69,75.7 ; J83.4 12.15,74.16 ; J83.4 13.69,74.16 ; J112.6 8.44,9.5 ; J112.6 6.64,11.29 ; J112.6 6.64,9.5 ; J112.6 8.44,11.29 ; J83.6 11.6,83.59 ; J83.6 8.82,80.81 ; J83.6 8.82,83.59 ; J83.6 11.6,80.81 ; 103.63,43.63 J110.14 ; J110.14 105.28,43.63 ; J110.14 103.63,45.27 ; J110.14 105.28,45.27 ; 77.62,148.65 J2.6 ; J74.4 110.36,109.41 ; J74.4 108.71,109.41 ; J74.4 110.36,107.76 ; J74.4 108.71,107.76 ; 94.27,144.64 J111.6 ; J111.6 96.07,142.85 ; J111.6 96.07,144.64 ; J111.6 94.27,142.85 ; 136.38,45.54 J110.1 ; J110.1 138.57,43.36 ; J110.1 138.57,45.54 ; J110.1 136.38,43.36 ; 83.97,145.97 J2.9 ; J2.9 83.97,147.83 ; J2.9 85.63,147.83 ; J2.9 85.63,145.97 ; J5.2 176.67,136.65 ; J5.2 175.02,138.3 ; J5.2 176.67,138.3 ; J5.2 175.02,136.65 ; TP11.1 18.72,135.24 ; TP11.1 16.21,132.73 ; TP11.1 18.72,132.73 ; TP11.1 16.21,135.24 ; J501.10 76.1,24.35 ; J501.10 76.1,22.64 ; J501.10 74.4,24.35 ; J501.10 74.4,22.64 ; 71.77,77.5 J517.2 ; J517.2 71.77,75.85 ; J517.2 73.42,75.85 ; J517.2 73.42,77.5 ; J501.8 73.56,24.35 ; J501.8 73.56,22.64 ; J501.8 71.86,22.64 ; J501.8 71.86,24.35 ; J85.3 13.74,146.5 ; J85.3 12.09,148.14 ; J85.3 12.09,146.5 ; J85.3 13.74,148.14 ; 122.05,51.68 J97.16 ; J97.16 123.63,50.11 ; J97.16 122.05,50.11 ; J97.16 123.63,51.68 ; 128.05,51.68 J97.10 ; J97.10 128.05,50.11 ; J97.10 129.63,50.11 ; J97.10 129.63,51.68 ; 21.77,71.31 J521.2 ; J521.2 23.42,71.31 ; J521.2 23.42,69.66 ; J521.2 21.77,69.66 ; J97.15 123.63,49.68 ; J97.15 123.63,48.11 ; J97.15 122.05,48.11 ; J97.15 122.05,49.68 ; 166.92,7.86 167.82,8.75 ; 166.92,7.86 166.03,6.96 ; 166.92,7.86 167.82,6.96 ; 166.92,7.86 166.03,8.75 ; 115,25.09 J120.11 ; 154.29,23.17 J23.1 154.29,21.28 ; 113.5,25.09 J120.10 ; J522.2 38.61,39.61 ; J522.2 38.61,37.96 ; J522.2 36.96,37.96 ; J522.2 36.96,39.61 ; 56.64,81.14 J516.2 ; J516.2 56.64,82.79 ; J516.2 58.29,81.14 ; J516.2 58.29,82.79 ; 55.33,15.57 J45.2 ; 102.86,134.95 J103.1 102.86,136.83 ; 69.34,124.86 J524.2 ; J524.2 70.99,124.86 ; J524.2 70.99,126.5 ; J524.2 69.34,126.5 ; 156.45,28.39 J122.7 157.88,28.39 ; J2.8 81.13,147.83 ; J2.8 79.47,147.83 ; J2.8 79.47,145.97 ; J9.2 174.25,87.89 ; J9.2 172.46,86.1 ; J9.2 174.25,86.1 ; J9.2 172.46,87.89 ; 154.93,58.09 J503.1 154.93,56.21 ; 129.1,25.73 J121.6 ; 117.21,25.32 J120.12 117.21,26.75 ; 136.59,25.73 J121.11 ; 136.17,113.93 J6.1 134.74,113.93 ; 138.8,27.39 J121.12 138.8,25.95 ; 172.81,115.9 J506.2
  BOTTOM w0.203: U36.2 120.58,2.27 120.65,2.2 120.65,2.14 v1(120.94,1.85) ; v1(15.76,100.71) 16.56,100.71 C515.2 ; U37.2 123.76,2.04 123.87,1.92 v1(123.87,1.56)
  BOTTOM w0.254: C519.2 24.97,109.22 24.97,108.05 v1(25.02,108)
  BOTTOM w0.305: C576.1 136.64,70.92 v1(136.92,71.2) ; C242.2 156.18,79.17 v1(156.45,78.9) ; C623.2 25.83,81.65 26.16,81.98 v1(26.24,81.98) ; C170.1 v1(148.29,95.26) ; v1(158.29,81.9) 158.51,82.12 C241.2 ; v1(178.66,88.89) 178.54,89.01 178.54,89.53 178.84,89.83 U503.4 ; C161.1 v1(155.14,96.4) ; R713.2 152.48,73.94 v1(152.45,73.9) ; C201.2 145.1,95.25 v1(145.48,95.63) ; C172.1 v1(145.73,96.9) ; C583.2 143.88,66.9 144.51,67.54 v1(144.84,67.54) ; C259.1 v1(145.08,82.13) ; C240.1 v1(157.28,84.56) ; C202.1 v1(142.52,94.82) ; C289.2 v1(139.45,78.9)
  BOTTOM w0.381: X2.2 v1(129.53,89.37) ; v1(30.16,50.8) 30.2,50.83 C778.2 ; v1(154.45,78.9) U15.W5 ; C789.1 74.9,104.07 74.62,103.79 74.62,102.88 v1(74.61,102.87) ; C828.1 v1(57.47,132.11) ; R859.2 v1(140.02,55.88) ; v1(36.69,83.21) 36.87,83.39 36.87,83.54 37.15,83.82 C547.2 ; v1(150.93,82.62) C250.2 150.93,81.29 C557.1 ; v1(68.28,66.48) 69.56,66.48 C753.1 ; v1(23.3,73.62) 23.3,72.89 23.69,72.5 C625.2 ; C166.2 v1(150.22,97.47) ; v1(160.45,78.9) U15.AE5 ; C689.1 v1(167.94,12.37) ; C283.2 v1(149.45,78.9) C281.2 ; v1(147.45,90.9) U15.M17 ; C212.2 v1(160.09,88.79) ; v1(155.45,87.9) U15.W14 ; v1(75.84,144.03) 76.2,143.67 U520.3 ; v1(113.29,67.01) 113.35,67.07 R663.2 ; v1(150.45,84.9) C251.2 ; U529.3 v1(87.39,107.54) ; v1(22.17,51.52) 22.64,51.99 C775.1 ; C502.1 v1(133.67,60.05) ; R593.1 v1(41.91,120.13) ; R148.2 v1(146.69,39.33) ; R114.1 136.22,99.38 v1(136.19,99.41) ; R595.1 v1(35.05,121.4) ; C209.2 v1(162.45,86.9) U15.AF14 C210.1 ; U15.D8 v1(139.45,80.9) ; v1(154.45,91.9) U15.W19 ; v1(104.2,92.87) 104.05,93.02 C698.1 ; R838.2 v1(58.45,124.24) ; C834.1 v1(96.76,118.54) ; U9.3 v1(176.3,28.02) ; R590.1 v1(121.72,10.45) ; U15.W16 v1(155.45,89.9) ; C164.2 v1(153.4,96.97) ; C520.1 v1(25.72,124.51) ; R95.1 v1(131.22,124.89) ; C200.2 v1(144.24,92.4) ; R646.2 v1(109.42,68.94) ; v1(161.9,106.67) 161.61,106.38 R36.2 ; C196.2 v1(147.45,92.9) C199.2 ; R662.2 v1(112.08,67.01) ; J103.1 101.92,136.73 C687.1 ; R821.1 v1(79.69,145.41) ; v1(139.45,90.9) U15.D17 ; C264.2 v1(140.45,81.9) ; C148.2 v1(168.21,105.3) ; R640.2 v1(133.15,61.84) ; C223.2 v1(145.09,87.4) ; C176.2 134.38,96.95 v1(134.28,97.05) ; X2.4 v1(132.29,85.93) ; C676.1 55.68,16.85 J45.2 ; U539.4 131.9,110.83 v1(132.65,111.58) ; v1(178.86,7.51) 178.86,7.42 178.64,7.2 C507.1 ; v1(71.8,62.72) 72.06,62.47 R751.1 ; R145.2 147.26,42.55 v1(147.45,42.74) ; U48.3 v1(103.86,65.09) ; R120.2 v1(168.46,85.61) ; U15.AG8 v1(163.45,80.9) ; C754.1 v1(71.23,53.64) ; v1(148.45,92.9) C195.2 ; C508.1 182.04,5.45 v1(181.91,5.31) ; v1(69.25,47.41) 68.96,47.12 C755.1 ; v1(67.89,145.55) 68.46,146.12 U569.3 ; C837.1 117.79,92.6 J73.1 ; C298.1 167.47,75.45 168.09,74.84 v1(168.09,74.78) ; v1(157.45,98.9) C162.2 ; R649.2 v1(11.54,31.11) ; R113.1 145.4,103.86 v1(145.45,103.9) ; U558.3 v1(27.34,115.79) ; v1(147.45,85.9) U15.M12 ; v1(66.47,122.67) 66.78,122.35 R198.1 ; C682.1 v1(125.41,37.06) ; C154.2 163.03,97.4 163.58,96.86 163.58,96.03 v1(163.45,95.9) ; R629.2 v1(12.5,134.73) ; v1(30.74,114.96) 31.24,115.46 C531.1 ; C159.2 v1(161.45,94.9) U15.AE21 ; C675.1 116.84,68.99 v1(116.92,69.07) ; U524.5 v1(164.15,144.93) ; R776.1 67.2,53.1 v1(67.19,53.1) ; C182.2 v1(159.95,89.69) ; v1(148.45,84.9) C254.2 ; R747.1 v1(78.23,60.56) ; C818.1 93.55,95.19 v1(93.23,94.87) ; C184.2 v1(157.73,93.78) ; C528.1 v1(35.76,75.2) ; C790.1 80.61,101.6 v1(78.42,101.6) ; v1(22.65,48.04) 23.11,48.5 R797.1 ; C800.1 v1(54.09,99.64) ; C548.1 35.85,83.82 v1(36.16,84.12) ; C549.2 21.91,124.09 21.53,124.47 v1(21.47,124.47) ; C792.2 75.48,110.65 v1(75.76,110.93) ; U15.M15 v1(147.45,87.9) ; v1(138.45,90.9) C205.2 ; U523.2 84.59,90.37 v1(84.59,89.51) ; C815.1 v1(168.27,130.77) ; C820.2 v1(65.73,127.95) ; C262.2 v1(141.45,80.9) ; C260.2 v1(143.12,83.3) ; v1(147.45,44.26) 147,43.81 C320.2 ; v1(117.64,73.64) 117.68,73.68 R661.2 ; C699.2 150.34,70.88 151.24,70.88 v1(151.3,70.83) ; C302.2 v1(152.59,72.37) ; C667.1 v1(130.49,32.79) ; v1(147.45,84.9) C256.2 ; v1(143.19,105.27) R105.2 R106.2 ; C836.1 v1(125.95,113.03) ; R581.1 v1(124.99,11.32) ; C786.1 19.55,52.27 v1(20.28,51.54) ; C819.1 v1(86.77,87.82) ; v1(162.45,90.9) U15.AF18 ; R660.2 v1(110.49,67.01) ; C585.2 v1(21.27,108.2) ; C521.2 20.64,121.34 v1(20.82,121.16) ; v1(159.45,98.9) U15.AC25 ; Q13.2 v1(59.96,138.89) ; C829.1 v1(58.1,116.76) ; C688.1 v1(86.75,141.09) ; v1(150.45,92.9) C193.2 ; U567.1 v1(177.49,27.39) ; v1(141.45,82.9) C263.2 ; C303.2 v1(145.62,72.16) ; R97.1 v1(131.22,121.89) ; C183.2 v1(158.24,92.4) ; C177.2 v1(168.03,93.14) ; R648.2 v1(11.52,32.38) ; C277.2 v1(156.45,78.9) ; C696.1 v1(13.76,6.71) ; C690.1 168.53,24.08 168.53,23.4 J105.1 ; C300.2 v1(159.5,72.32) ; R90.1 v1(131.22,126.39) ; C206.2 134.82,94.09 v1(134.51,93.78) ; v1(158.45,78.9) C276.2 ; U502.2 v1(181.93,93.69) ; R144.2 v1(149.92,41.71) ; v1(162.45,80.9) C235.2 ; v1(163.45,89.9) 163.04,89.5 C208.2 ; v1(69.38,89.28) 68.9,88.8 DN10.1 ; v1(161.45,83.9) C237.2 ; C141.2 v1(141.22,128.16) ; U15.E13 v1(141.45,85.9) ; v1(81.96,96.07) 81.09,96.07 C788.1 ; R157.2 v1(113.97,87.43) ; R829.1 v1(46.18,140.97) ; C71.2 v1(178.47,142.95) ; R666.2 v1(118.43,66.85) ; R123.2 v1(176.15,86.25) ; v1(154.45,92.9) C189.2 ; C261.2 v1(142.8,80.44) ; v1(155.45,98.9) C163.2 ; U15.W17 v1(155.45,90.9) ; v1(26.35,53.34) 26.67,53.66 C774.1 ; v1(130.64,91.49) 131.05,91.08 C231.1 ; v1(152.45,78.9) U15.U5 ; U15.AF19 v1(162.45,91.9) ; C290.2 v1(134.74,77.9) ; C266.2 v1(139.45,82.9) ; C814.1 160.34,129.85 v1(159.14,129.85) ; C249.2 v1(152.45,84.9) C248.2 ; C622.2 v1(27.51,74.63) ; C247.2 v1(154.32,82.11) ; C178.2 164.47,93.93 v1(164.45,93.9) ; v1(155.45,84.9) C243.2 ; v1(148.45,98.9) U15.M26 ; v1(148.45,91.9) U15.M19 ; DN12.1 65.72,88.7 v1(65.95,88.93) ; U15.D28 v1(140.45,101.9) ; v1(153.45,84.9) C246.2 ; R667.2 v1(108.15,72.48) ; C697.1 106.68,86.05 U54.2 ; U500.2 132.08,94.71 v1(131.43,95.35) ; C190.2 v1(155.15,95.25) ; R664.2 v1(114.62,66.96) ; v1(149.45,92.9) C194.2 ; DN9.1 v1(73.13,87.95) ; C833.1 v1(102.55,121.08) ; C282.2 v1(149.75,80.97) ; D50.3 v1(50.48,133.91) ; C188.2 v1(155.45,92.9) C185.2 ; C150.2 158.55,105.56 v1(158.49,105.61) ; C511.2 v1(10.77,101.71) ; J104.1 16.73,11.53 17.25,11.53 C695.1 ; C835.1 139.38,111.73 v1(139.64,111.99) ; v1(138.37,105.38) 138.23,105.24 C153.2 ; R523.2 v1(69.24,13.86) ; R632.2 v1(133.15,55.08) ; C299.1 v1(165.3,72.32) ; C149.2 v1(165.35,106.25) ; R642.2 v1(131.13,63.14) ; C291.2 v1(134.74,75.04) ; U528.2 92.13,91.33 v1(92.13,92.74) ; U58.3 80.65,105.92 v1(81.05,105.52) ; C776.1 28.18,46.32 v1(28.77,45.73) ; v1(140.45,85.9) C230.2 ; v1(147.45,89.9) U15.M16 ; R828.2 v1(60.64,131.65) ; U567.3 180.34,27.26 v1(181.1,26.5) ; v1(153.45,92.9) C191.2 ; v1(161.12,53.97) 161.33,54.18 C317.2 ; v1(140.45,83.9) C265.2 ; C228.2 v1(140.45,87.9) ; v1(134.74,81.44) 134.94,81.64 135.56,81.64 C269.2 ; J2.6 v1(78.46,148.35) ; U566.4 97.77,117.54 v1(97.47,117.83) ; C10.1 v1(173.77,23.06) ; U15.AG23 v1(162.45,95.9) ; C211.1 v1(160.45,85.9) ; C321.1 v1(150.5,25.92) ; C811.1 v1(169.86,140.36) ; v1(139.21,72.28) 139.5,72.57 C304.2 ; v1(147.89,80.49) 147.44,80.04 C284.2 ; C666.1 v1(125.41,32.74) ; U15.W18 v1(155.45,91.9) ; R839.1 v1(89.4,108.38) ; v1(62.58,146.8) 64.19,146.8 U568.3 ; C147.2 v1(140.65,118.86) ; C203.2 v1(142.8,90.6) ; C136.2 v1(141.22,146.25) ; C830.1 v1(145.73,51.94) ; C137.2 v1(140.65,136.96) ; C279.2 v1(155.03,80.26) ; R103.1 v1(131.22,115.89) ; U538.4 127.02,125.99 v1(127.37,126.34) ; C222.2 v1(147.45,86.9) ; C810.1 v1(174.28,140.06) ; U11.3 v1(167.53,18.74) ; v1(153.45,98.9) C165.2 ; v1(149.45,84.9) C253.2 ; C252.2 v1(149.75,82.62) ; v1(135.51,80.96) 135.24,80.69 C301.2 ; v1(142.45,98.9) C173.2 ; C817.1 v1(155.89,135.25) ; C232.1 v1(135.64,87) ; R96.1 v1(131.22,123.39) ; v1(147.45,78.9) C285.2 ; C654.1 v1(163.46,19.4) ; v1(154.45,84.9) C245.2 ; v1(152.45,92.9) C192.2 ; R665.2 v1(115.57,66.98) ; v1(161.45,96.9) C158.2 ; C204.2 v1(141.45,91.9) ; v1(146.45,98.9) C171.2 ; C517.2 v1(127.43,93.26) ; Q1.2 v1(176.3,22.56) ; v1(155.45,85.9) U15.W12 ; v1(162.45,97.9) C156.2 ; C175.1 v1(140.45,98.9) ; R133.2 v1(149.89,45.61) ; C529.2 v1(38.53,74.43) ; v1(161.45,79.9) U15.AE7 ; U15.AF10 v1(162.45,82.9) ; R210.2 v1(166.57,111.97) ; C683.1 v1(130.49,37.13) ; v1(154.45,87.9) U15.W15 ; R645.2 v1(132.72,63.06) ; C268.2 v1(134.61,84.89) ; D51.1 v1(41.69,137.62) ; R99.1 v1(131.22,120.39) ; U9.1 v1(173.36,29.29) ; v1(36.95,119.41) 37.03,119.49 R594.1 ; v1(142.45,77.9) C287.2 ; C832.1 v1(133.59,138) ; C757.2 68.51,53.51 68.22,53.22 v1(68.2,53.22) ; C239.2 v1(159.09,81.4) ; C213.2 v1(158.5,88.38) ; v1(140.45,96.9) U15.E23 ; U15.E5 v1(140.45,77.9) ; C225.2 v1(144.66,86.4) ; R149.2 v1(145.41,39.33) ; R100.1 v1(131.22,118.89) ; J2.7 v1(88.18,149.9) ; C207.2 v1(167.32,87.67) ; C138.1 v1(65.09,140.06) ; R818.1 76.09,95.75 v1(76.77,95.07) ; R101.1 v1(131.22,117.39) ; v1(155.45,86.9) U15.W13 ; v1(143.45,78.9) U15.H5 ; C258.2 v1(145.95,81.69) ; C167.2 v1(151.97,95.5) ; C816.1 v1(155.87,133.35) ; R155.1 v1(34.2,85.72) ; v1(147.45,91.9) U15.M18 ; v1(161.45,81.9) C236.2 ; R108.1 v1(171.54,128.07) ; v1(150.45,98.9) C168.2 ; v1(161.45,98.9) U15.AF26 ; v1(141.45,90.9) C226.2 ; R138.2 v1(146.71,45.09) ; C224.2 v1(144.66,88.4) ; C257.2 v1(145.09,85.4) ; C151.1 v1(150.06,105.77)
  BOTTOM w0.635: U524.9 168.41,140.34 v1(168.72,140.03) ; C758.2 v1(94.26,48.29) ; C823.2 59.86,92.68 59.09,91.92 59.09,90.73 v1(58.59,90.22) ; v1(74,118.08) 74,119.74 73.34,120.4 C802.2 ; v1(45.81,128.78) 46.85,128.78 47.61,129.54 47.66,129.54 C822.2 ; v1(65.49,126.5) 63.89,126.5 C827.1 ; C825.2 78.02,117.04 v1(79.44,117.04) ; v1(65.06,135) C803.2 ; C805.2 79.06,140.06 v1(79.31,140.31) ; C821.2 47.66,119.38 v1(45.63,119.38) ; C804.2 80.89,121.26 80.18,120.56 80.18,119.08 v1(79.78,118.68) ; C759.2 v1(94.26,52.63) ; C824.2 v1(45.71,124.46) ; v1(87.17,53.4) 86.51,52.74 C762.2 ; C826.2 v1(66.36,90.5) ; C58.2 v1(69.53,145.12) ; U59.11 v1(62.55,121.08)
  BOTTOM w1.016: D32.1 v1(60.88,75.17)
  vias: v1(26.35,52.07) v1(26.35,50.8) v1(26.35,49.53) v1(27.62,52.07) v1(27.62,50.8) v1(27.62,49.53) v1(28.89,53.34) v1(28.89,52.07) v1(28.89,50.8) v1(28.89,49.53) v1(30.16,53.34) v1(30.16,52.07) v1(30.16,49.53) v1(65.72,60.96) v1(65.72,59.69) v1(65.72,58.42) v1(65.72,57.15) v1(66.99,60.96) v1(66.99,59.69) v1(66.99,58.42) v1(66.99,57.15) v1(68.26,60.96) v1(68.26,59.69) v1(68.26,58.42) v1(68.26,57.15) v1(69.53,60.96) v1(69.53,59.69) v1(69.53,58.42) v1(69.53,57.15) v1(74.61,101.6) v1(74.61,100.33) v1(74.61,99.06) v1(75.88,101.6) v1(75.88,100.33) v1(75.88,99.06) v1(77.15,102.87) v1(77.15,101.6) v1(77.15,100.33) v1(77.15,99.06) v1(78.42,102.87) v1(78.42,100.33) v1(78.42,99.06) v1(86.65,126.39) v1(86.65,125.4) v1(87.46,125.89) v1(88.28,126.39) v1(88.28,125.4) v1(88.89,139.01) v1(88.89,138) v1(88.89,136.98) v1(88.89,135.97) v1(88.89,134.95) v1(88.89,133.93) v1(88.89,132.92) v1(88.89,131.9) v1(88.89,130.89) v1(90.45,8.9) v1(90.84,9.55) v1(91.35,8.86) v1(148.27,43.5) v1(149.1,44.26) v1(149.1,42.74) v1(155.18,51.33) v1(156.2,51.33) v1(156.81,49.78) v1(157.82,49.78) v1(159.81,51.01) v1(159.86,50.17) v1(160.83,51.27) v1(160.77,50.34) v1(161.25,56.82) v1(162.27,56.82) v1(163.28,56.82) v1(170.63,65.41) v1(170.63,62.86) v1(170.63,60.33) v1(170.73,66.7) v1(170.68,64.17) v1(170.67,61.58) v1(185.62,41.67) v1(185.63,34.58) v1(186.64,40.97) v1(186.64,33.92) v1(186.68,42.33) v1(186.66,35.24)
